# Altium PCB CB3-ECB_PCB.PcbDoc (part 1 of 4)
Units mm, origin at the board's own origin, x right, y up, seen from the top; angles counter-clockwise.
Board outline 195 x 139 mm, 4 copper layers (Top Layer, Layer 1, Layer 2, Bottom Layer), stack 1.56 mm thick; 363 components, 264 nets, 1430 pads, 630 vias.
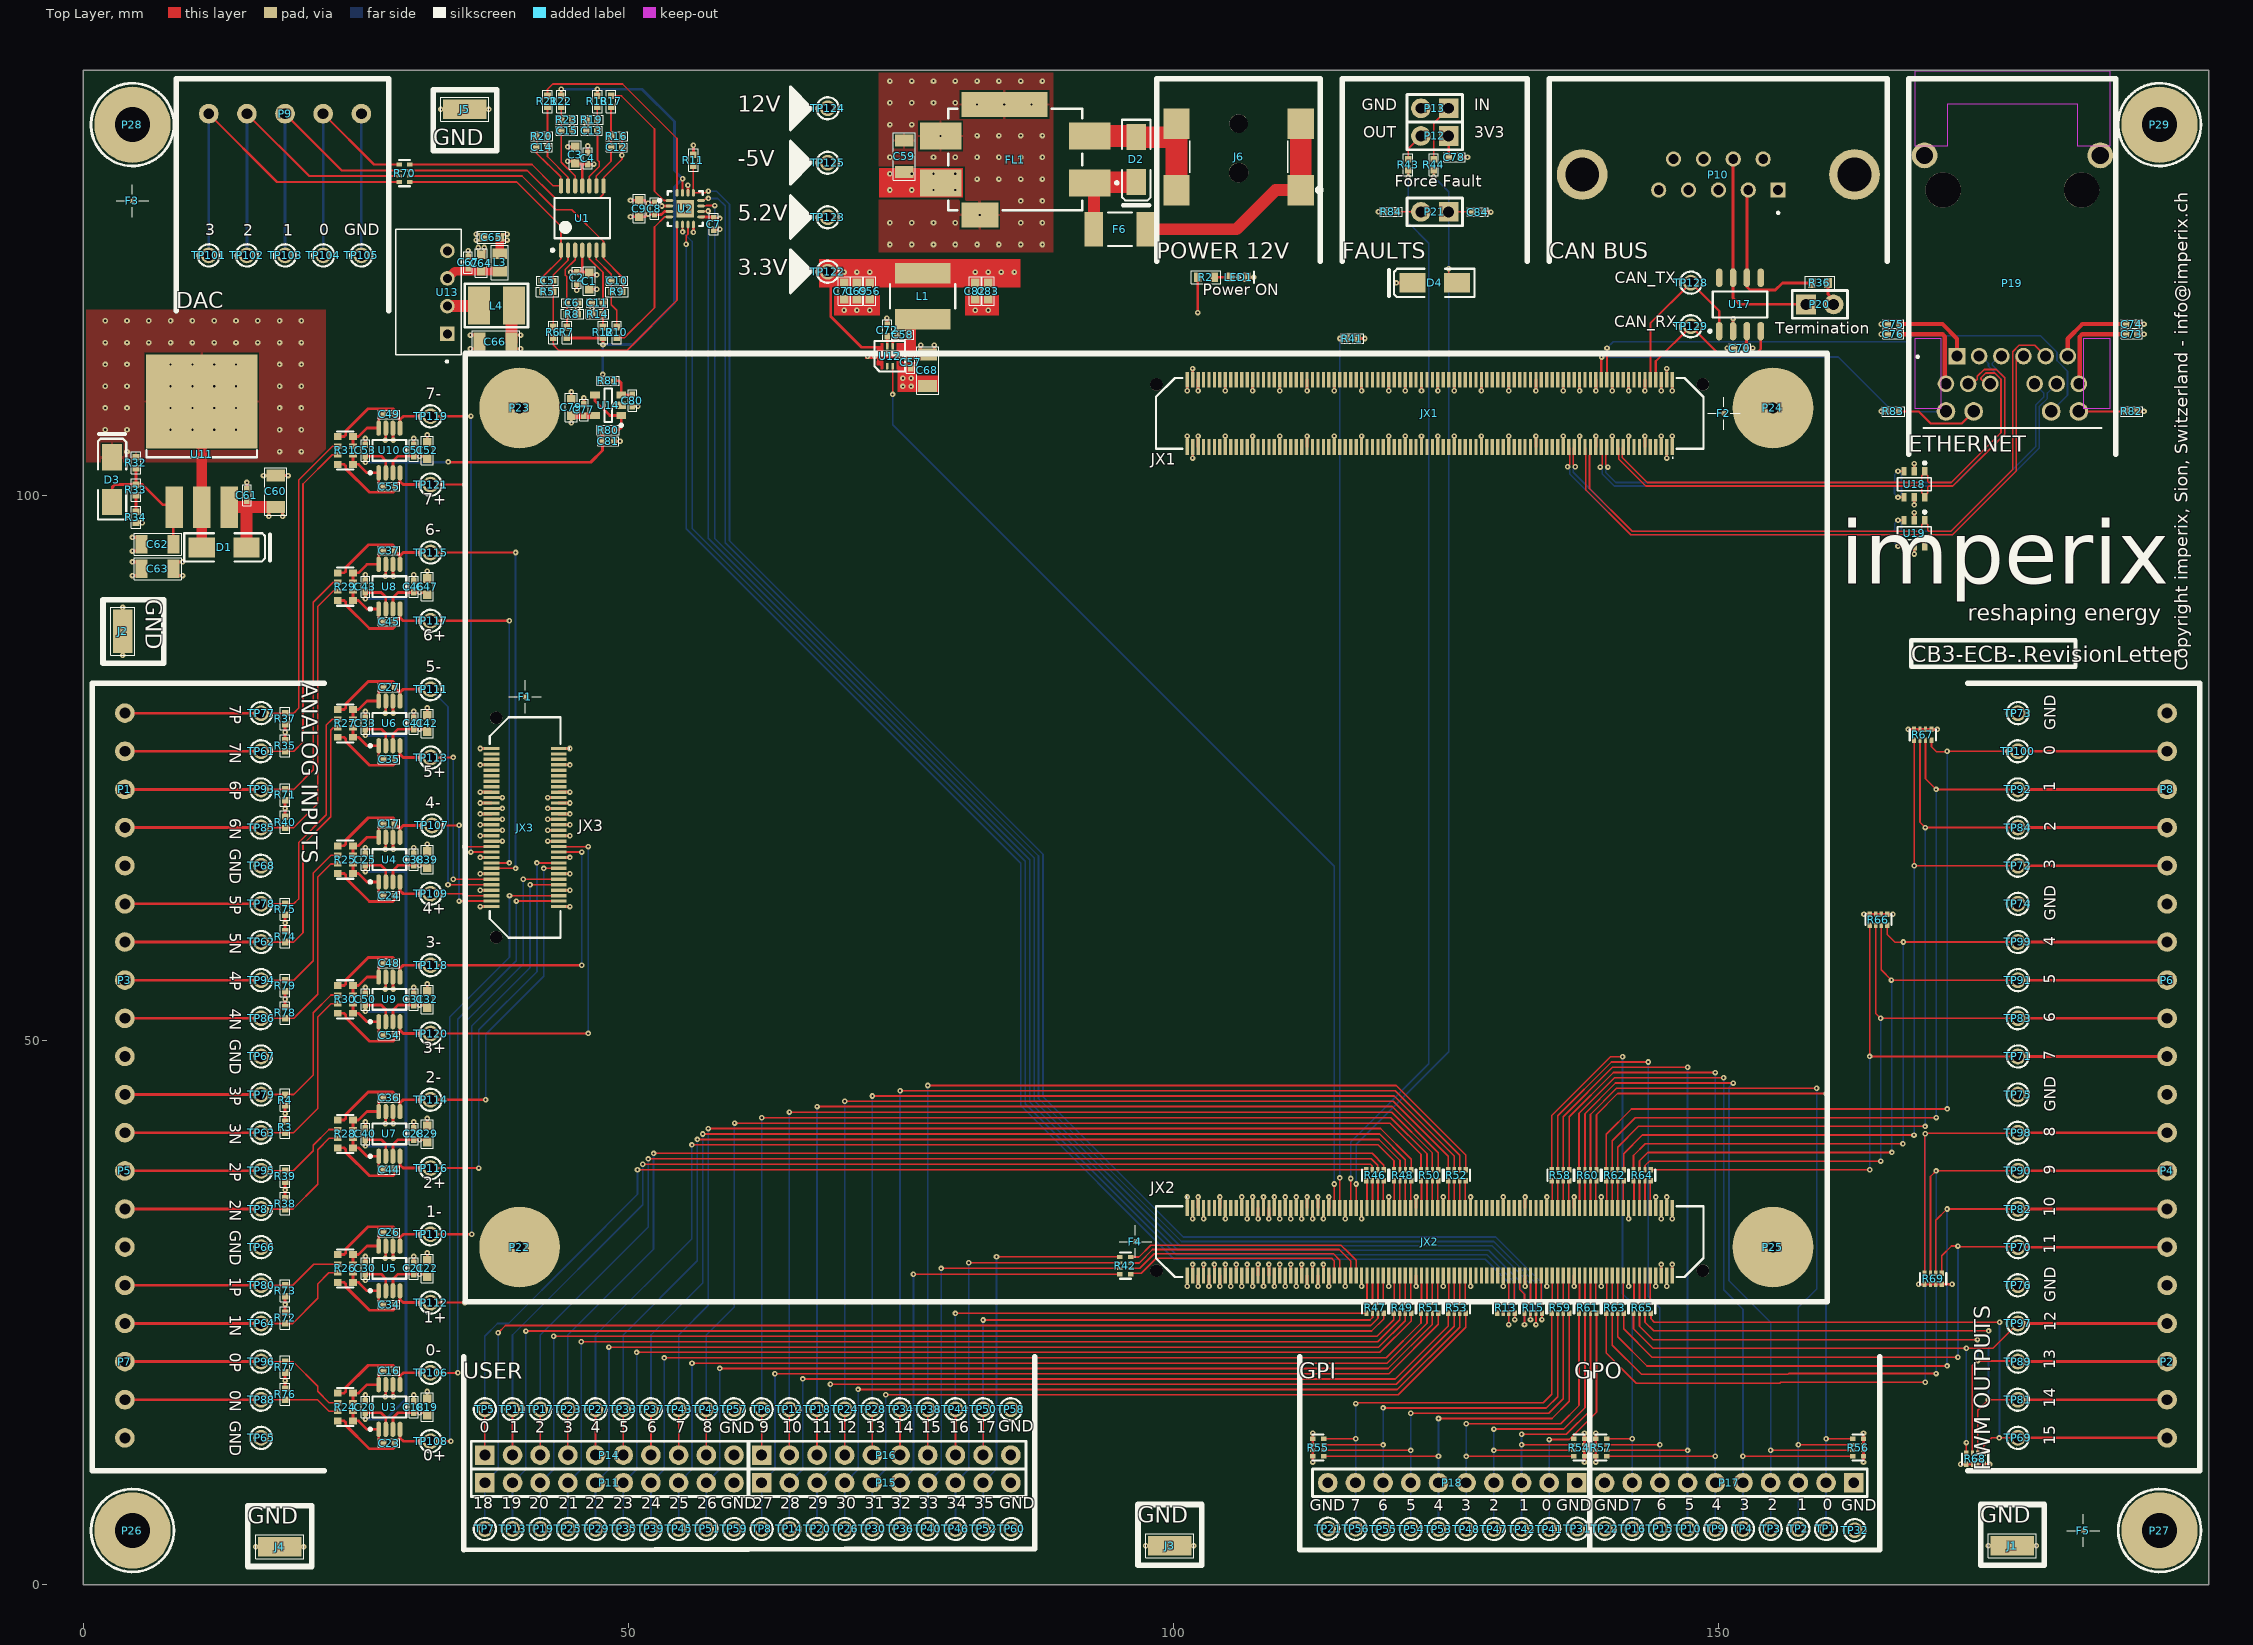
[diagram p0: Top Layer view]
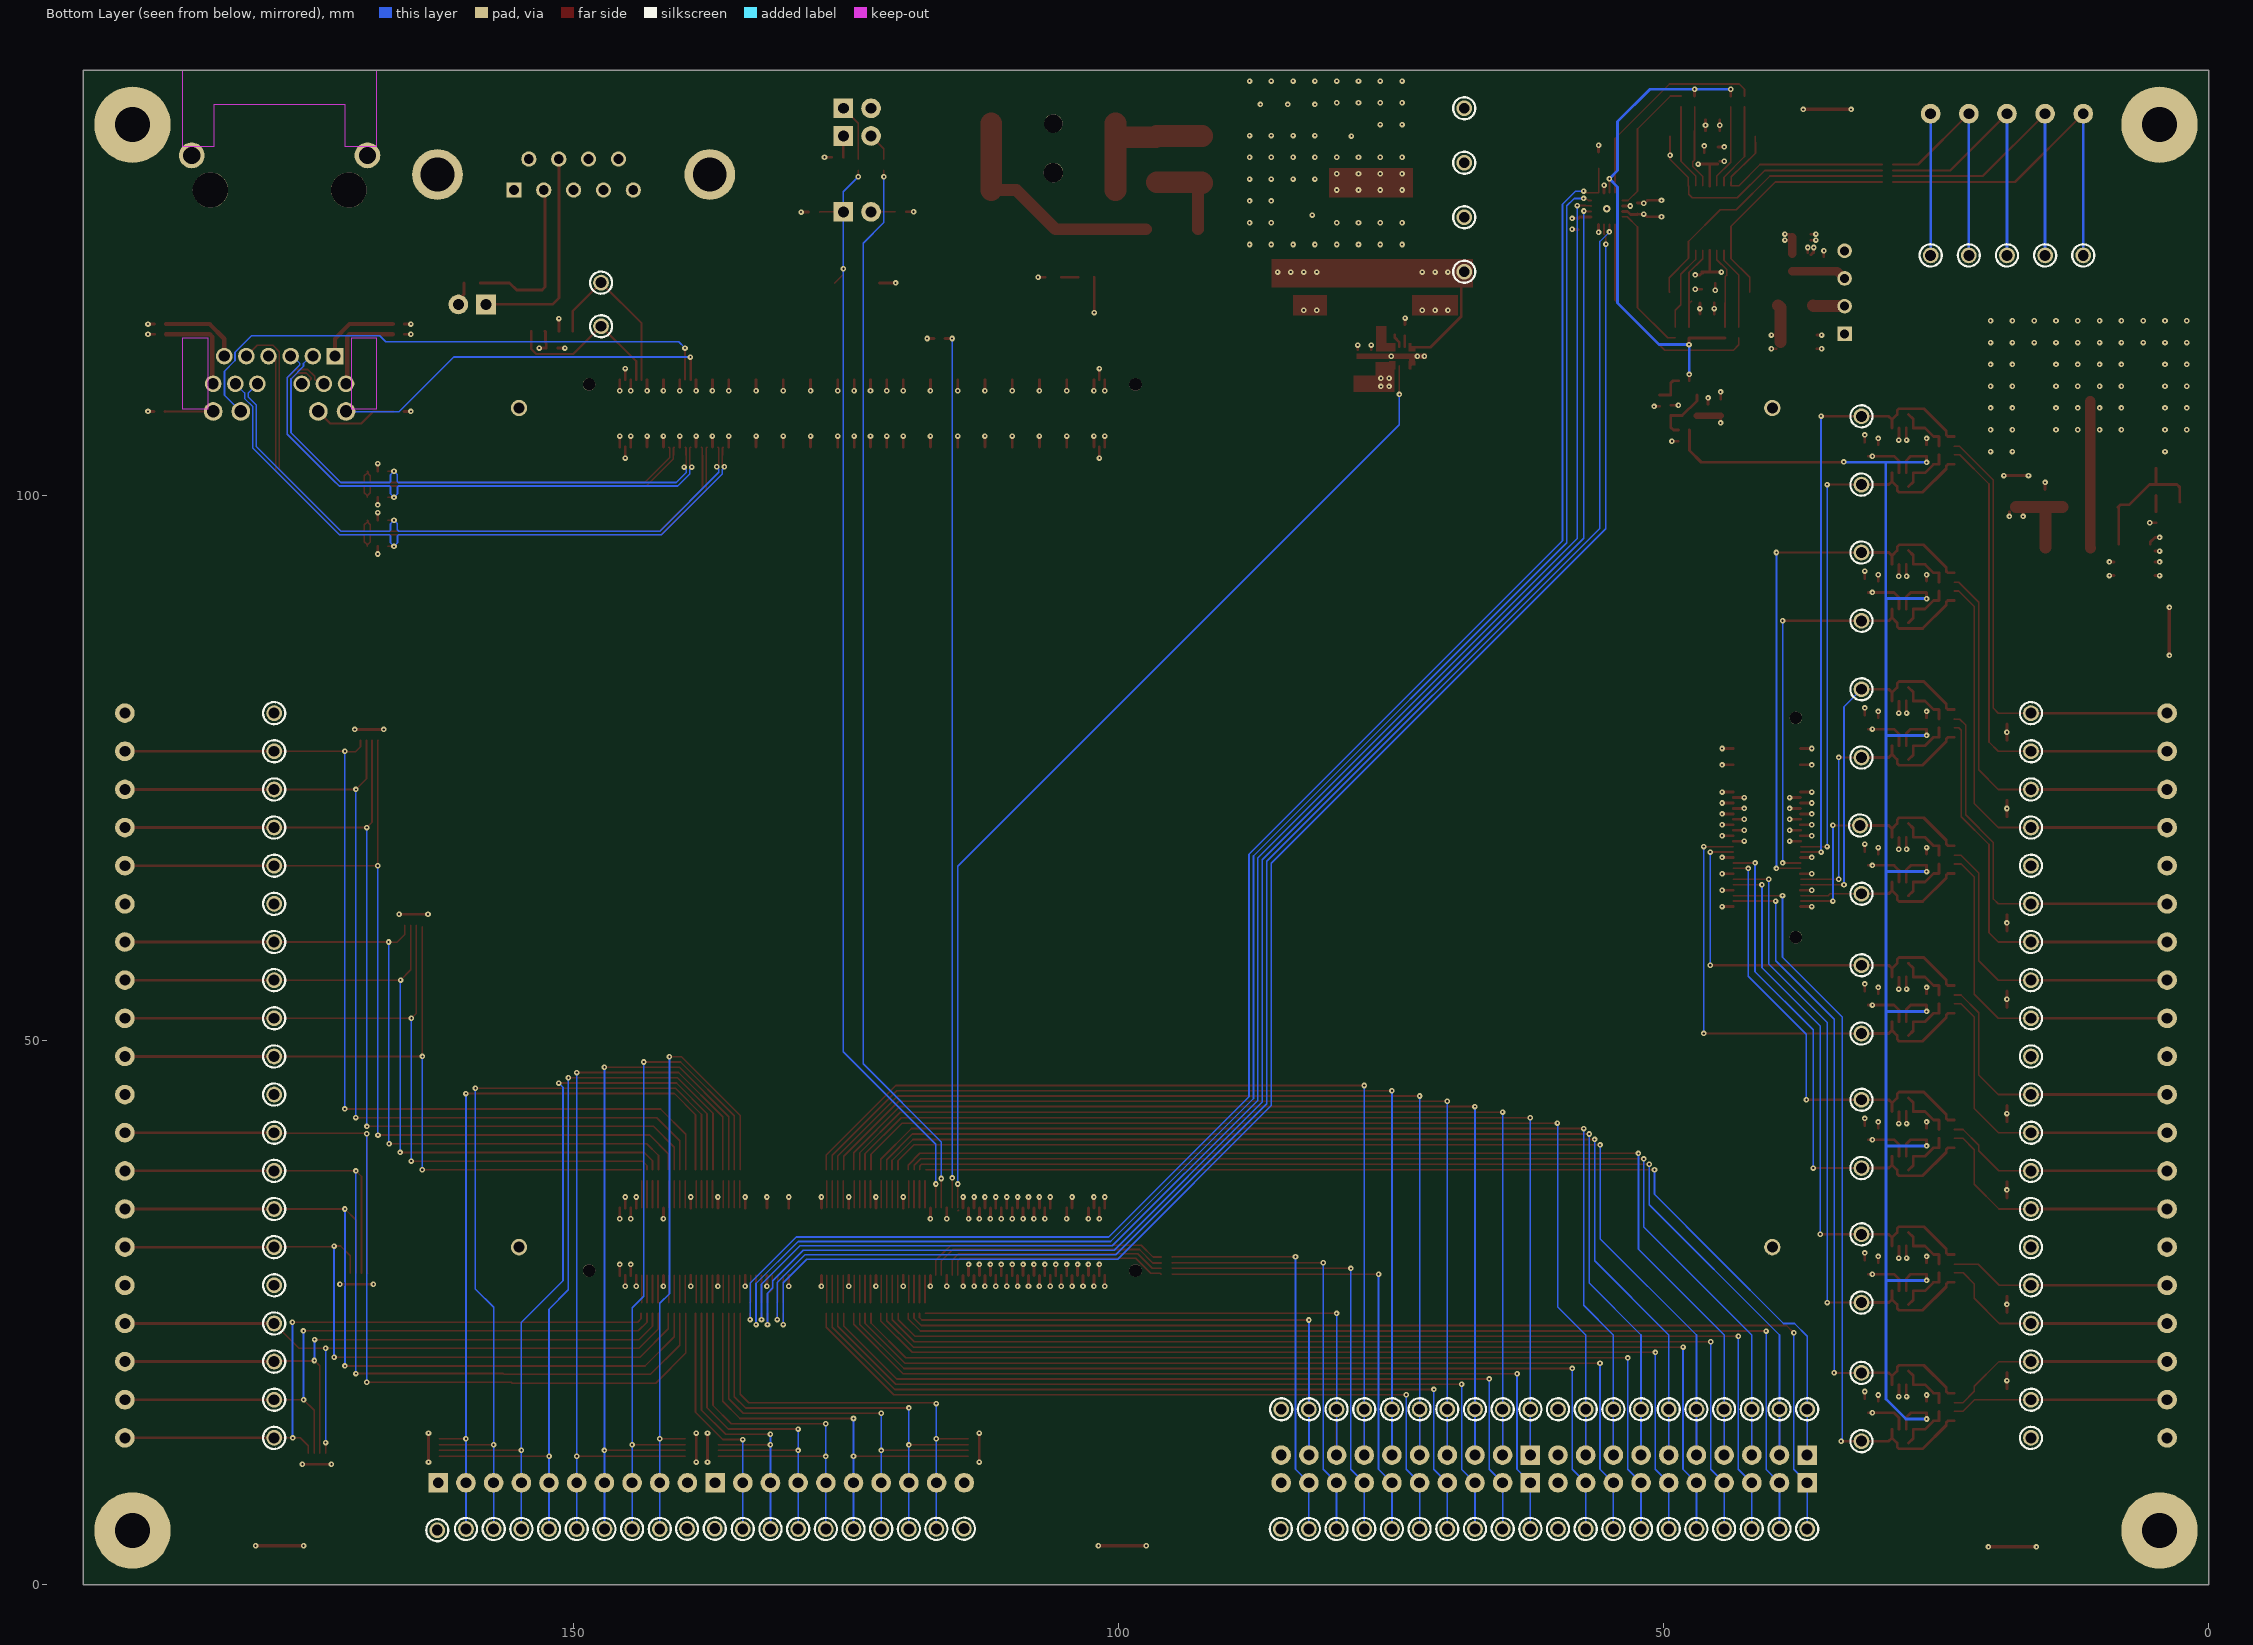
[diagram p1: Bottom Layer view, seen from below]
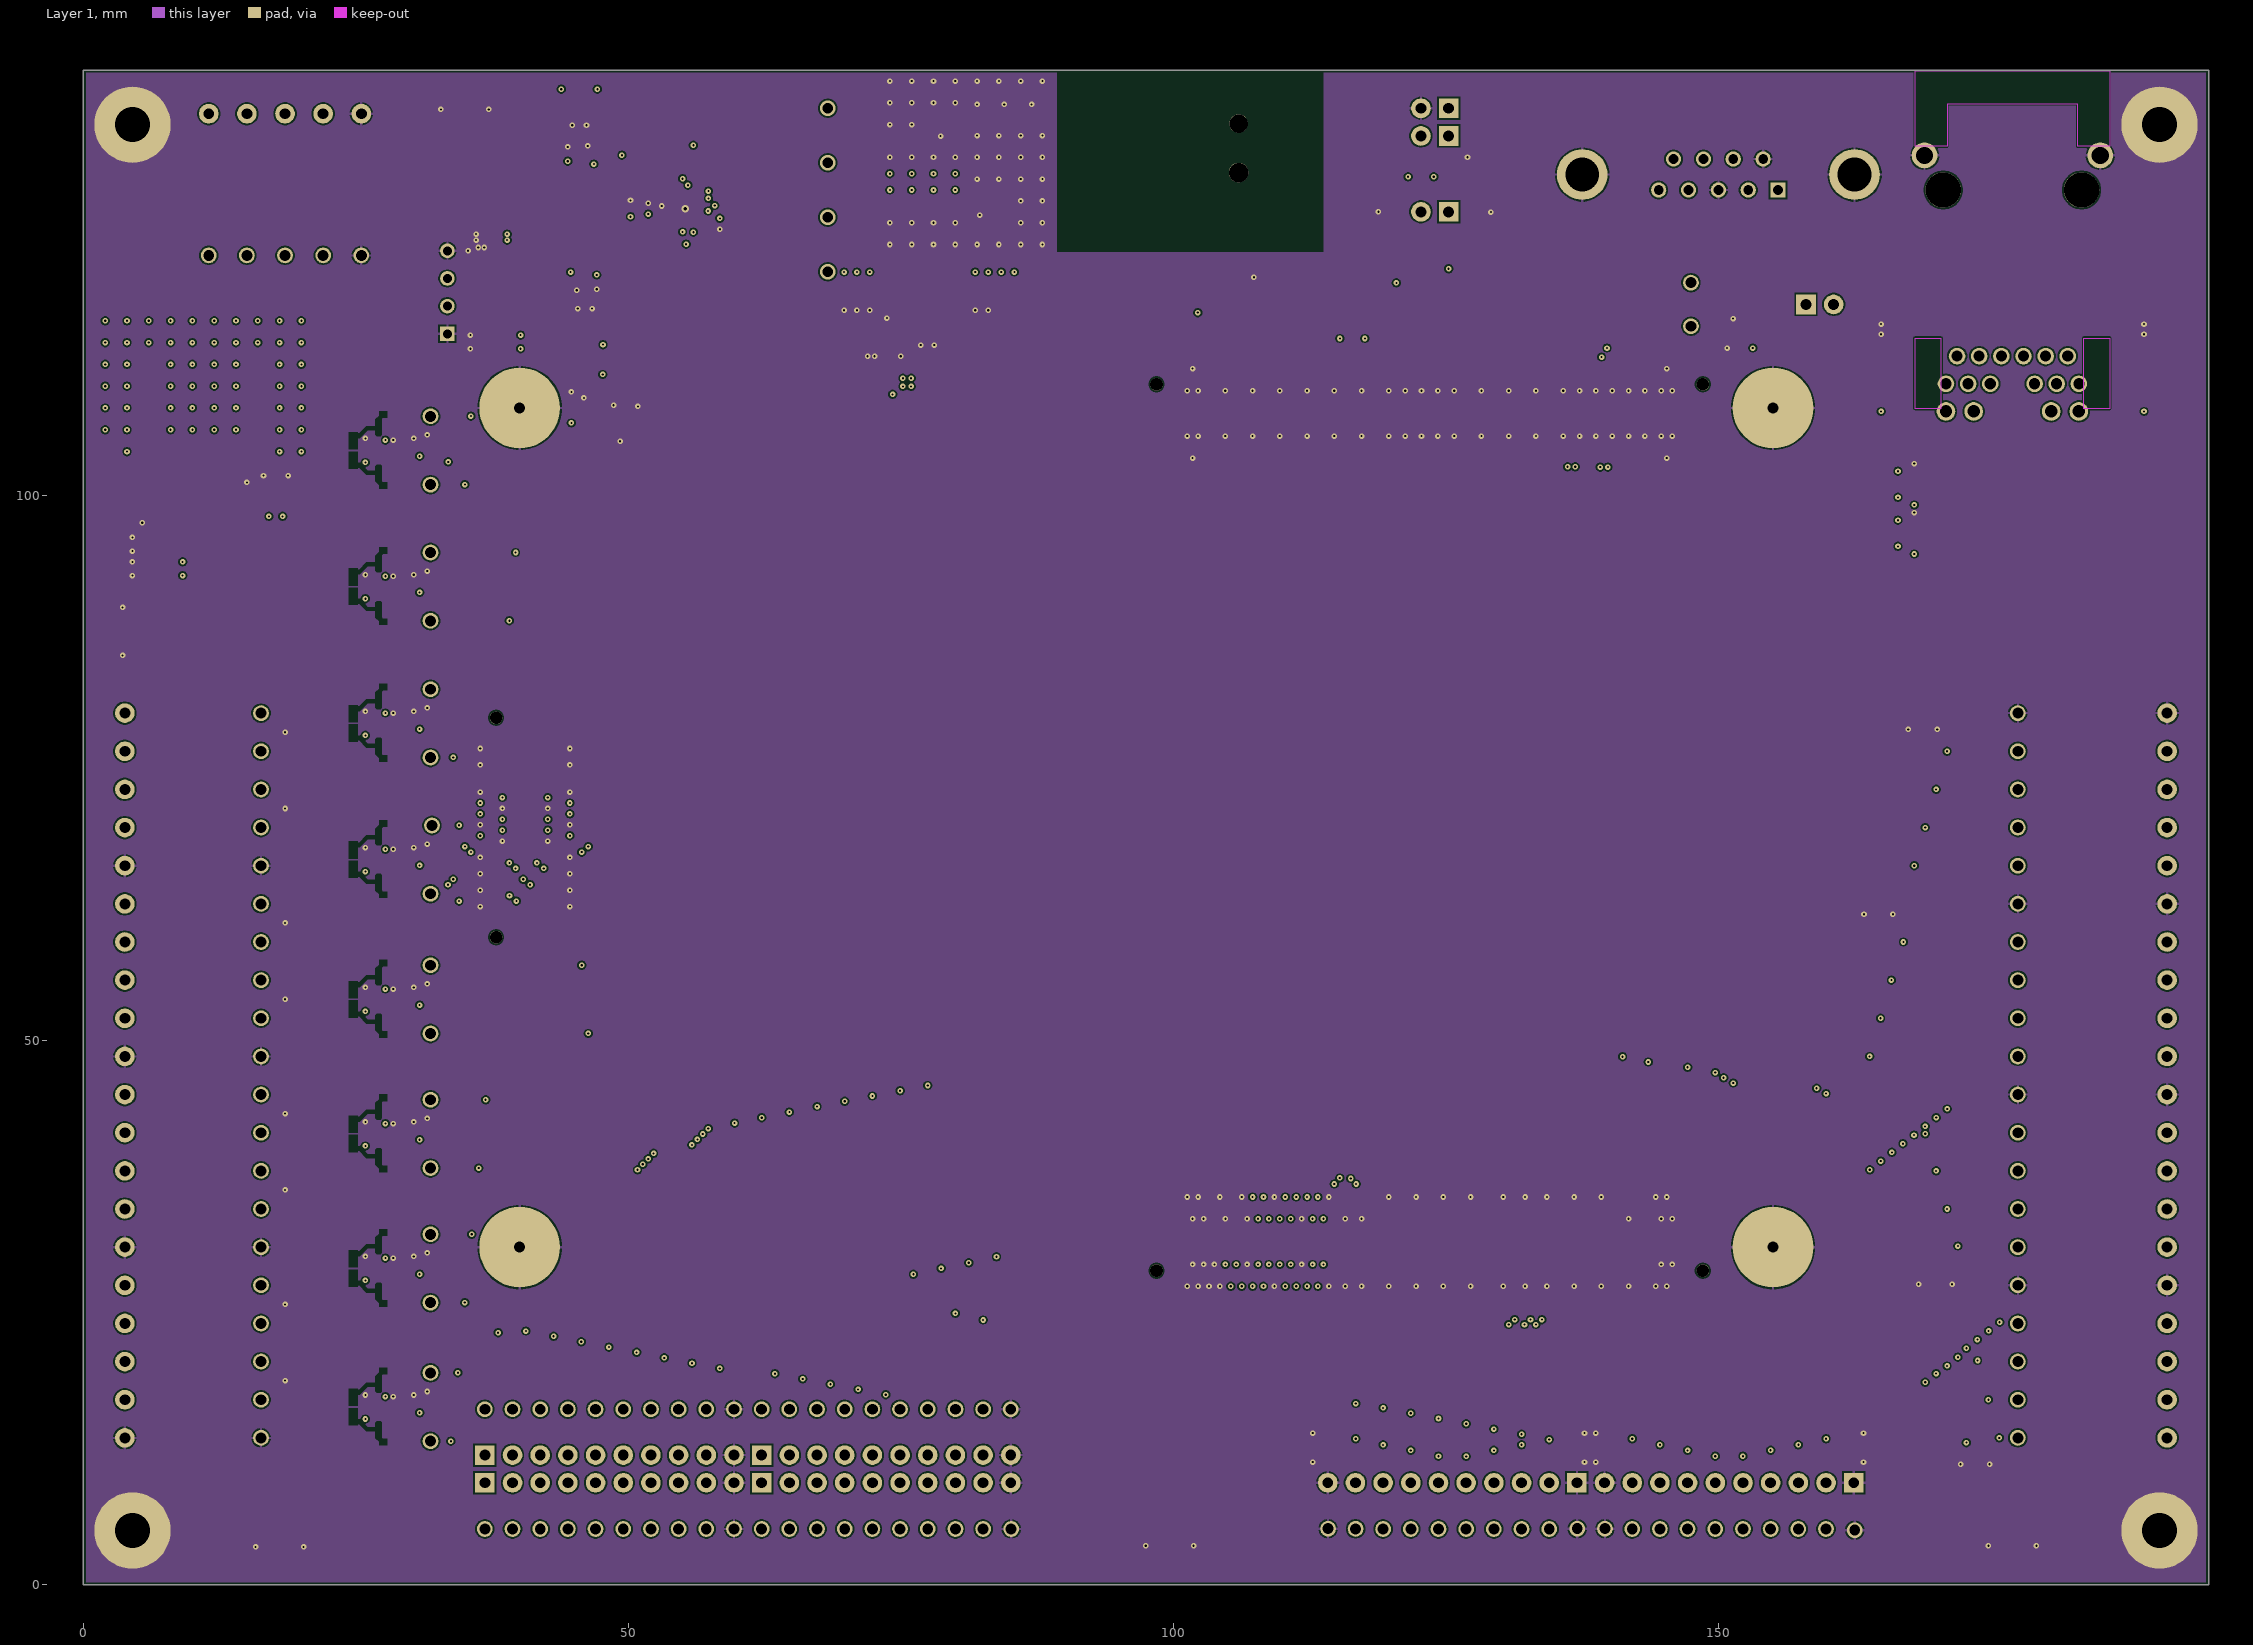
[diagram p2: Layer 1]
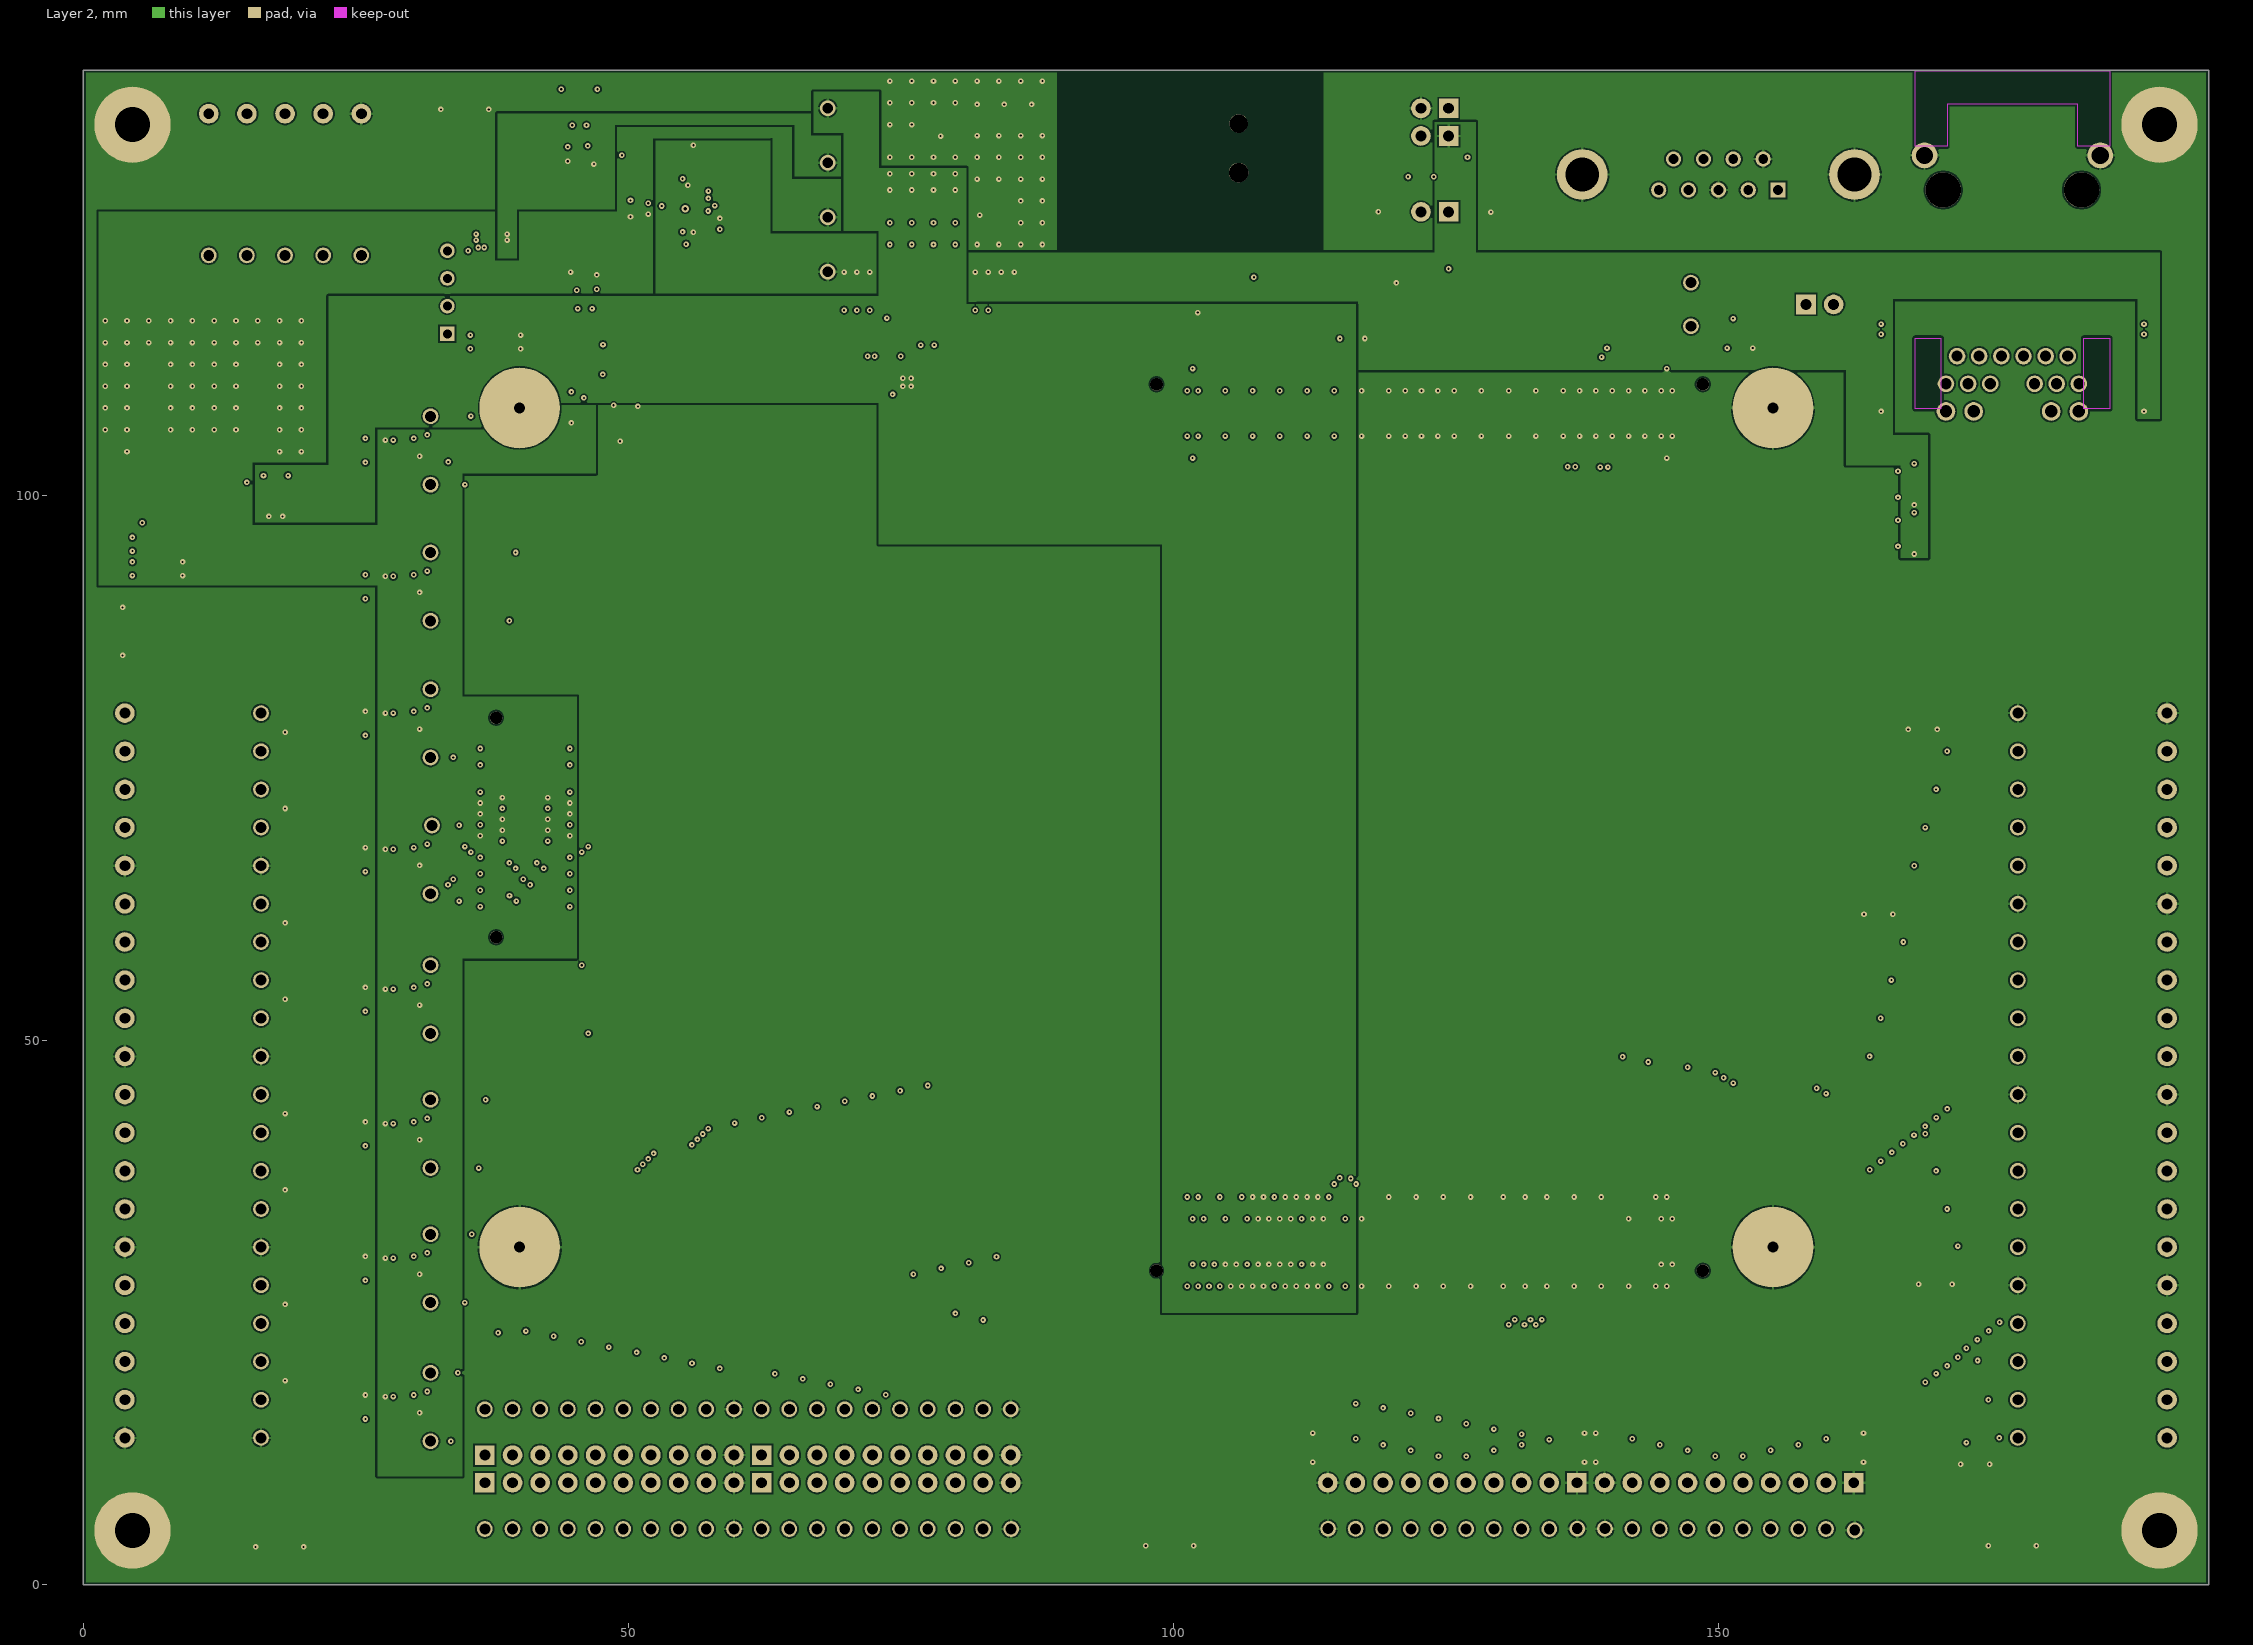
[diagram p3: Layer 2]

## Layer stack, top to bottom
Top Solder: solder mask 0.0102, Solder Resist, Dk 3.5
Top Layer: signal copper 0.035
Dielectric 1: prepreg 0.11, PP-006, Dk 4.29
Layer 1: signal copper 0.035
Dielectric4: dielectric 1.2, FR-4, Dk 4.8
Layer 2: signal copper 0.035
Dielectric 2: prepreg 0.11, PP-006, Dk 4.29
Bottom Layer: signal copper 0.035
Bottom Solder: solder mask 0.0102, Solder Resist, Dk 3.5

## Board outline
0,0 0,139 195,139 195,0

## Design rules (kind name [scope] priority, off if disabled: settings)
BoardOutlineClearance [All] p1: gap=0.25 ignorepadtopadclearanceinfootprint=FALSE
Clearance Clearance_Layer1 [OnLayer('Layer 2')] p1: gap=0.152 ignorepadtopadclearanceinfootprint=FALSE except(0.25: Fill-Fill Fill-Poly Fill-Region Poly-Poly Poly-Region Region-Region)
Clearance [All] p2: gap=0.152 ignorepadtopadclearanceinfootprint=FALSE
ComponentClearance [All] p1: gap=0 collisioncheckmode=3 verticalgap=2540 showdistances=FALSE
DiffPairsRouting [InDifferentialPairClass('All Differential Pairs')] p1: maxlimit=0.18 minlimit=0.114 mostfreqgap=0.18 toplayer_mingap=0.18 toplayer_minwidth=0.15 toplayer_maxwidth=0.15 toplayer_prefwidth=0.15 bottomlayer_mingap=0.18 bottomlayer_minwidth=0.15 bottomlayer_maxwidth=0.15 bottomlayer_prefwidth=0.15 impedanceprofiledriven=TRUE impedanceprofileid={5B398267-E329-4BF6-97D7-3C22107C88F5} impedanceprofilevalue=100.000000 maxuncoupledlength=12.7
HoleSize [All] p1: absolutevalues=TRUE maxlimit=5 minlimit=0.2 maxpercent=80.000 minpercent=20.000
HoleToHoleClearance [All] p1: gap=0.3 allowstackedmicrovias=TRUE
MinimumAnnularRing [All] p1: minimumring=0.152
MinimumSolderMaskSliver [All] p1 off: minsoldermaskwidth=0.254
PasteMaskExpansion PasteMaskExpansion_J5_nomask [InComponent('J5')] p1: expansion=-10
PasteMaskExpansion PasteMaskExpansion_BGA [HasFootprint('FGG484')] p2 off: expansion=-0.175
PasteMaskExpansion PasteMaskExpansion_5mm [((PadXSize_TopLayer > 4.99) and (PadYSize_TopLayer > 4.99)) or ((PadXSize_BottomLayer > 4.99) and (PadYSize_BottomLayer > 4.99))] p3 off: expansion=-1
PasteMaskExpansion PasteMaskExpansion_2mm5 [((PadXSize_TopLayer > 2.49) and (PadYSize_TopLayer > 2.49)) or ((PadXSize_BottomLayer > 2.49) and (PadYSize_BottomLayer > 2.49))] p4 off: expansion=-0.5
PasteMaskExpansion PasteMaskExpansion_1mm [((PadXSize_TopLayer > 0.99) and (PadYSize_TopLayer > 0.99)) or ((PadXSize_BottomLayer > 0.99) and (PadYSize_BottomLayer > 0.99))] p5 off: expansion=-0.2
PasteMaskExpansion PasteMaskExpansion_default [All] p6 off: expansion=-0.05
PermittedLayers [All] p1: toplayerpermitted=TRUE bottomlayerpermitted=TRUE
PlaneClearance [All] p1: clearance=0.152
PlaneConnect PlaneConnect_pad [InPadClass('All Pads')] p1: planeconnectstyle=Relief reliefexpansion=0.2 reliefentries=4 reliefconductorwidth=0.2 reliefairgap=0.2
PlaneConnect [All] p2: planeconnectstyle=Direct reliefexpansion=0.508 reliefentries=4 reliefconductorwidth=0.254 reliefairgap=0.254
PolygonConnect [All] p1: thpad.connectstyle=Relief thpad.reliefconductorwidth=0.25 thpad.reliefentries=4 thpad.polygonreliefangle="90 Angle" thpad.airgapwidth=0.15 smdpad.connectstyle=Relief smdpad.reliefconductorwidth=0.25 smdpad.reliefentries=4 smdpad.polygonreliefangle="90 Angle" smdpad.airgapwidth=0.15 via.connectstyle=Direct via.reliefconductorwidth=0.254 via.reliefentries=4 via.polygonreliefangle="90 Angle" via.airgapwidth=0.254
RoutingVias [All] p1: holewidth=0.2 width=0.45 viastyle="Through Hole" minholewidth=0.2 minwidth=0.4 maxholewidth=2 maxwidth=4
SMDNeckDown [All] p1 off: percent=95.000
SMDToCorner [All] p1: distance=0
SilkToSilkClearance [All] p1 off: silktosilkclearance=0.254
SilkToSolderMaskClearance [IsPad] p1 off: minsilkscreentomaskgap=0.254 clearancetoexposedcopper=TRUE
SolderMaskExpansion [All] p1: expansion=0.051 istentingtop=FALSE
Width Width_power [InNetClass('PWR')] p1: maxlimit=2 minlimit=0.25 preferedwidth=0.4
Width [All] p2: maxlimit=2 minlimit=0.152 preferedwidth=0.152
20 further rules are at their usual default settings.

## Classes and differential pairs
component class Power: C56 C57 C58 C59 C60 C61 C62 C63 C64 C65 C66 C67 C68 C69 C71 C72 C82 C83 D1 D2 D3 F1 F2 F3 F4 F5 F6 FL1 J6 L1 L3 L4 LED1 P22 P23 P24 P25 P26 P27 P28 P29 R2 R32 R33 R34 TP122 TP123 TP124 TP125 U11 U12 U13
component class BBoard-JX2: C78 C84 D4 JX2 P2 P4 P6 P8 P11 P12 P13 P14 P15 P16 P17 P18 P21 R41 R42 R43 R44 R46 R47 R48 R49 R50 R51 R52 R53 R54 R55 R56 R57 R58 R59 R60 R61 R62 R63 R64 R65 R66 R67 R68 R69 R84
component class BBoard-JX1: C70 C73 C74 C75 C76 JX1 P10 P19 P20 R36 R82 R83 TP128 TP129 U17 U18 U19
net class PWR: 3V3 5V2 +12V -5V GND NetC58_1 NetC64_1 NetD2_A NetD2_K NetF6_1 NetL4_2
component class ADC: C16 C17 C18 C19 C20 C21 C22 C23 C24 C25 C26 C27 C28 C29 C30 C31 C32 C33 C34 C35 C36 C37 C38 C39 C40 C41 C42 C43 C44 C45 C46 C47 C48 C49 C50 C51 C52 C53 C54 C55 C77 C79 C80 C81 JX3 P1 P3 P5 P7 R3 R4 R24 R25 R26 R27 R28 R29 R30 R31 R35 R37 R38 R39 R40 R71 R72 R73 R74 R75 R76 R77 R78 R79 R80 R81 TP106 TP107 TP108 TP109 TP110 TP111 TP112 TP113 TP114 TP115 TP116 TP117 TP118 TP119 TP120 TP121 U3 U4 U5 U6 U7 U8 U9 U10 U14
component class DAC: C1 C2 C3 C4 C5 C6 C7 C8 C9 C10 C11 C12 C13 C14 C15 P9 R5 R6 R7 R8 R9 R10 R11 R12 R13 R14 R15 R16 R17 R18 R19 R20 R21 R22 R23 R70 TP101 TP102 TP103 TP104 TP105 U1 U2
component class "Test points": J1 J2 J3 J4 J5 TP1 TP2 TP3 TP4 TP5 TP6 TP7 TP8 TP9 TP10 TP11 TP12 TP13 TP14 TP15 TP16 TP17 TP18 TP19 TP20 TP21 TP22 TP23 TP24 TP25 TP26 TP27 TP28 TP29 TP30 TP31 TP32 TP33 TP34 TP35 TP36 TP37 TP38 TP39 TP40 TP41 TP42 TP43 TP44 TP45 TP46 TP47 TP48 TP49 TP50 TP51 TP52 TP53 TP54 TP55 TP56 TP57 TP58 TP59 TP60 TP61 TP62 TP63 TP64 TP65 TP66 TP67 TP68 TP69 TP70 TP71 TP72 TP73 TP74 TP75 TP76 TP77 TP78 TP79 TP80 TP81 TP82 TP83 TP84 TP85 TP86 TP87 TP88 TP89 TP90 TP91 TP92 TP93 TP94 TP95 TP96 TP97 TP98 TP99 TP100
differential pair PHY_MDI3: +PHY_MDI3_P -PHY_MDI3_N
differential pair PHY_MDI2: +PHY_MDI2_P -PHY_MDI2_N
differential pair PHY_MDI1: +PHY_MDI1_P -PHY_MDI1_N
differential pair PHY_MDI0: +PHY_MDI0_P -PHY_MDI0_N

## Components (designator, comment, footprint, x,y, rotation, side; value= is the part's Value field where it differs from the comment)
C1 "CAP-10UF-10V-X5R-0603-10%" CAPC1608L(0603) 46.417,119.639 r90 top value=10uF
C2 "CAP-100NF-25V-X7R-0402-10%" CAPC1005L(0402) 45.272,119.942 r90 top value=100nF
C3 "CAP-10UF-10V-X5R-0603-10%" CAPC1608L(0603) 45.125,131.213 r90 top value=10uF
C4 "CAP-100NF-25V-X7R-0402-10%" CAPC1005L(0402) 46.27,130.91 r90 top value=100nF
C5 "CAP-56PF-50V-C0G-0402-1%" CAPC1005L(0402) 42.587,119.665 r180 top value=56pF
C6 "CAP-10NF-25V-X7R-0402-10%" CAPC1005L(0402) 44.865,117.633 r180 top value=10nF
C7 "CAP-100NF-25V-X7R-0402-10%" CAPC1005L(0402) 57.828,124.871 r90 top value=100nF
C8 "CAP-100NF-25V-X7R-0402-10%" CAPC1005L(0402) 52.4,126.3 r270 top value=100nF
C9 "CAP-10UF-10V-X5R-0603-10%" CAPC1608L(0603) 51,126.3 r270 top value=10uF
C10 "CAP-56PF-50V-C0G-0402-1%" CAPC1005L(0402) 48.963,119.665 r0 top value=56pF
C11 "CAP-10NF-25V-X7R-0402-10%" CAPC1005L(0402) 47.151,117.633 r0 top value=10nF
C12 "CAP-56PF-50V-C0G-0402-1%" CAPC1005L(0402) 48.941,131.908 r0 top value=56pF
C13 "CAP-10NF-25V-X7R-0402-10%" CAPC1005L(0402) 46.647,133.432 r0 top value=10nF
C14 "CAP-56PF-50V-C0G-0402-1%" CAPC1005L(0402) 42.057,131.908 r180 top value=56pF
C15 "CAP-10NF-25V-X7R-0402-10%" CAPC1005L(0402) 44.377,133.432 r180 top value=10nF
C16 "CAP-12PF-50V-C0G-0402-5%" CAPC1005L(0402) 28.049,19.638 r0 top value=12pF
C17 "CAP-12PF-50V-C0G-0402-5%" CAPC1005L(0402) 28.049,69.867 r0 top value=12pF
C18 "CAP-100NF-25V-X7R-0402-10%" CAPC1005L(0402) 30.305,16.331 r270 top value=100nF
C19 "CAP-10UF-10V-X5R-0603-10%" CAPC1608L(0603) 31.548,16.331 r270 top value=10uF
C20 "CAP-1UF-6.3V-X5R-0402-5%" CAPC1005L(0402) 25.875,16.331 r270 top value=1uF
C21 "CAP-100NF-25V-X7R-0402-10%" CAPC1005L(0402) 30.305,29.044 r270 top value=100nF
C22 "CAP-10UF-10V-X5R-0603-10%" CAPC1608L(0603) 31.548,29.044 r270 top value=10uF
C23 "CAP-12PF-50V-C0G-0402-5%" CAPC1005L(0402) 28.049,13.025 r0 top value=12pF
C24 "CAP-12PF-50V-C0G-0402-5%" CAPC1005L(0402) 28.049,63.253 r0 top value=12pF
C25 "CAP-1UF-6.3V-X5R-0402-5%" CAPC1005L(0402) 25.875,66.56 r270 top value=1uF
C26 "CAP-12PF-50V-C0G-0402-5%" CAPC1005L(0402) 28.049,32.351 r0 top value=12pF
C27 "CAP-12PF-50V-C0G-0402-5%" CAPC1005L(0402) 28.049,82.364 r0 top value=12pF
C28 "CAP-100NF-25V-X7R-0402-10%" CAPC1005L(0402) 30.305,41.389 r270 top value=100nF
C29 "CAP-10UF-10V-X5R-0603-10%" CAPC1608L(0603) 31.548,41.389 r270 top value=10uF
C30 "CAP-1UF-6.3V-X5R-0402-5%" CAPC1005L(0402) 25.875,29.044 r270 top value=1uF
C31 "CAP-100NF-25V-X7R-0402-10%" CAPC1005L(0402) 30.305,53.733 r270 top value=100nF
C32 "CAP-10UF-10V-X5R-0603-10%" CAPC1608L(0603) 31.548,53.733 r270 top value=10uF
C33 "CAP-1UF-6.3V-X5R-0402-5%" CAPC1005L(0402) 25.875,79.057 r270 top value=1uF
C34 "CAP-12PF-50V-C0G-0402-5%" CAPC1005L(0402) 28.049,25.737 r0 top value=12pF
C35 "CAP-12PF-50V-C0G-0402-5%" CAPC1005L(0402) 28.049,75.75 r0 top value=12pF
C36 "CAP-12PF-50V-C0G-0402-5%" CAPC1005L(0402) 28.049,44.695 r0 top value=12pF
C37 "CAP-12PF-50V-C0G-0402-5%" CAPC1005L(0402) 28.049,94.911 r0 top value=12pF
C38 "CAP-100NF-25V-X7R-0402-10%" CAPC1005L(0402) 30.305,66.56 r270 top value=100nF
C39 "CAP-10UF-10V-X5R-0603-10%" CAPC1608L(0603) 31.548,66.56 r270 top value=10uF
C40 "CAP-1UF-6.3V-X5R-0402-5%" CAPC1005L(0402) 25.875,41.389 r270 top value=1uF
C41 "CAP-100NF-25V-X7R-0402-10%" CAPC1005L(0402) 30.305,79.057 r270 top value=100nF
C42 "CAP-10UF-10V-X5R-0603-10%" CAPC1608L(0603) 31.548,79.057 r270 top value=10uF
C43 "CAP-1UF-6.3V-X5R-0402-5%" CAPC1005L(0402) 25.875,91.604 r270 top value=1uF
C44 "CAP-12PF-50V-C0G-0402-5%" CAPC1005L(0402) 28.049,38.082 r0 top value=12pF
C45 "CAP-12PF-50V-C0G-0402-5%" CAPC1005L(0402) 28.049,88.398 r0 top value=12pF
C46 "CAP-100NF-25V-X7R-0402-10%" CAPC1005L(0402) 30.305,91.604 r270 top value=100nF
C47 "CAP-10UF-10V-X5R-0603-10%" CAPC1608L(0603) 31.548,91.604 r270 top value=10uF
C48 "CAP-12PF-50V-C0G-0402-5%" CAPC1005L(0402) 28.049,57.04 r0 top value=12pF
C49 "CAP-12PF-50V-C0G-0402-5%" CAPC1005L(0402) 28.049,107.408 r0 top value=12pF
C50 "CAP-1UF-6.3V-X5R-0402-5%" CAPC1005L(0402) 25.875,53.733 r270 top value=1uF
C51 "CAP-100NF-25V-X7R-0402-10%" CAPC1005L(0402) 30.305,104.101 r270 top value=100nF
C52 "CAP-10UF-10V-X5R-0603-10%" CAPC1608L(0603) 31.548,104.101 r270 top value=10uF
C53 "CAP-1UF-6.3V-X5R-0402-5%" CAPC1005L(0402) 25.875,104.101 r270 top value=1uF
C54 "CAP-12PF-50V-C0G-0402-5%" CAPC1005L(0402) 28.049,50.426 r0 top value=12pF
C55 "CAP-12PF-50V-C0G-0402-5%" CAPC1005L(0402) 28.049,100.794 r0 top value=12pF
C56 "CAP-10UF-10V-X5R-0603-10%" CAPC1608L(0603) 72.15,118.725 r90 top value=10uF
C57 "CAP-100NF-25V-X7R-0402-10%" CAPC1005L(0402) 75.9,112.175 r270 top value=100nF
C58 "CAP-100NF-25V-X7R-0402-10%" CAPC1005L(0402) 75.2,114.725 r180 top value=100nF
C59 "CAP-10UF-25V-X5R-1206-10%" CAPC3216L(1206) 75.3,131.1 r270 top value=10uF
C60 "CAP-10UF-25V-X5R-1206-10%" CAPC3216L(1206) 17.65,100.35 r270 top value=10uF
C61 "CAP-100NF-25V-X7R-0402-10%" CAPC1005L(0402) 15,100 r270 top value=100nF
C62 "CAP-10UF-25V-X5R-1206-10%" CAPC3216L(1206) 6.8,95.5 r0 top value=10uF
C63 "CAP-10UF-25V-X5R-1206-10%" CAPC3216L(1206) 6.8,93.25 r0 top value=10uF
C64 "CAP-10UF-10V-X5R-0603-10%" CAPC1608L(0603) 36.5,121.3 r90 top value=10uF
C65 "CAP-10UF-10V-X5R-0603-10%" CAPC1608L(0603) 37.45,123.675 r180 top value=10uF
C66 "CAP-10UF-25V-X5R-1206-10%" CAPC3216L(1206) 37.808,114.062 r0 top value=10uF
C67 "CAP-100NF-25V-X7R-0402-10%" CAPC1005L(0402) 35.3,121.35 r90 top value=100nF
C68 "CAP-10UF-25V-X5R-1206-10%" CAPC3216L(1206) 77.45,111.475 r270 top value=10uF
C69 "CAP-10UF-10V-X5R-0603-10%" CAPC1608L(0603) 70.975,118.725 r90 top value=10uF
C70 "CAP-100NF-25V-X7R-0402-10%" CAPC1005L(0402) 152,113.5 r0 top value=100nF
C71 "CAP-10UF-10V-X5R-0603-10%" CAPC1608L(0603) 69.8,118.725 r90 top value=10uF
C72 "CAP-1UF-6.3V-X5R-0402-5%" CAPC1005L(0402) 73.75,115.125 r270 top value=1uF
C73 "CAP-100NF-25V-X7R-0402-10%" CAPC1005L(0402) 187.95,114.763 r180 top value=100nF
C74 "CAP-100NF-25V-X7R-0402-10%" CAPC1005L(0402) 187.95,115.7 r180 top value=100nF
C75 "CAP-100NF-25V-X7R-0402-10%" CAPC1005L(0402) 166.075,115.7 r0 top value=100nF
C76 "CAP-100NF-25V-X7R-0402-10%" CAPC1005L(0402) 166.075,114.763 r0 top value=100nF
C77 "CAP-100NF-25V-X7R-0402-10%" CAPC1005L(0402) 45.925,107.825 r270 top value=100nF
C78 "CAP-100NF-25V-X7R-0402-10%" CAPC1005L(0402) 125.8,131 r180 top value=100nF
C79 "CAP-10UF-10V-X5R-0603-10%" CAPC1608L(0603) 44.775,108.05 r270 top value=10uF
C80 "CAP-1UF-6.3V-X5R-0402-5%" CAPC1005L(0402) 50.375,108.675 r90 top value=1uF
C81 "CAP-1UF-6.3V-X5R-0402-5%" CAPC1005L(0402) 48.15,104.95 r180 top value=1uF
C82 "CAP-10UF-10V-X5R-0603-10%" CAPC1608L(0603) 81.825,118.725 r90 top value=10uF
C83 "CAP-10UF-10V-X5R-0603-10%" CAPC1608L(0603) 83.025,118.725 r90 top value=10uF
C84 "CAP-100NF-25V-X7R-0402-10%" CAPC1005L(0402) 127.95,125.975 r180 top value=100nF
D1 "MBRA340T3G" DO-214AC 12.91,95.2 r0 top
D2 "SMAJ15A-TR" DO-214AC 96.6,130.8 r270 top value=975pF
D3 "MBRA340T3G" DO-214AC 2.625,101.425 r90 top
D4 "MBRA340T3G" DO-214AC 124,119.475 r180 top
F1 "Fiducial" Fiducial050 40.53,81.505 r0 top
F2 "Fiducial" Fiducial050 150.53,107.505 r0 top
F3 "Fiducial" Fiducial050 4.5,127 r0 top
F4 "Fiducial" Fiducial050 96.53,31.505 r0 top
F5 "Fiducial" Fiducial050 183.5,5 r0 top
F6 "1812L110/16DR" "PTC Fuse(1812)" 95.1,124.4 r180 top value=180mR
FL1 "BNX024H01L" FP-BNX02-MFG 85.5,130.8 r180 top
J1 "1625854-1" TP-3216L(1206) 177,3.6 r0 top
J2 "1625854-1" TP-3216L(1206) 3.6,87.5 r270 top
J3 "1625854-1" TP-3216L(1206) 99.67,3.6 r0 top
J4 "1625854-1" TP-3216L(1206) 18,3.5 r180 top
J5 "1625854-1" TP-3216L(1206) 35,135.4 r0 top
J6 "PJ-002AH-SMT-TR" PJ-002AH-SMT-TR 111.7,128 r270 top locked
JX1 "BSH-090-01-F-D-A" BSH-090-01-F-D-A 123.53,107.505 r270 top locked
JX2 "BSH-090-01-F-D-A" BSH-090-01-F-D-A 123.53,31.505 r90 top locked
JX3 "BSH-030-01-L-D-A" BSH-030-01-L-D-A 40.53,69.505 r0 top locked
L1 "VLS6045EX-3R3N" VLS6045EX 77,118.25 r90 top value=3.3uH
L3 "ILHB0805ER601V" RESC2012L(0805) 38.2,121.35 r90 top value="600Ω 2A"
L4 "84223C" "Inductor 8400 Serie" 37.9,117.4 r180 top value=22uH
LED1 "LTST-C193KGKT-5A" LED0603_GREEN 106,120 r0 top
P1 "1988985" 1988985 3.8,73 r180 top locked
P2 "1988985" 1988985 191.2,20.5 r0 top locked
P3 "1988985" 1988985 3.8,55.5 r180 top locked
P4 "1988985" 1988985 191.2,38 r0 top locked
P5 "1988985" 1988985 3.8,38 r180 top locked
P6 "1988985" 1988985 191.2,55.5 r0 top locked
P7 "1988985" 1988985 3.8,20.5 r180 top locked
P8 "1988985" 1988985 191.2,73 r0 top locked
P9 "1988985" 1988985 18.5,135 r90 top locked
P10 "LD09P33E4GV00LF" LD09P33E4GV00LF 155.5,128 r180 top locked
P11 "M20-9731045" M20-9731045 36.834,9.381 r180 top
P12 "M20-9990245" M20-9990245 125.27,132.96 r0 top
P13 "M20-9990245" M20-9990245 125.27,135.5 r0 top
P14 "M20-9731045" M20-9731045 36.834,11.921 r180 top
P15 "M20-9731045" M20-9731045 62.234,9.381 r180 top
P16 "M20-9731045" M20-9731045 62.234,11.921 r180 top
P17 "M20-9731045" M20-9731045 162.437,9.381 r0 top
P18 "M20-9731045" M20-9731045 137.037,9.381 r0 top
P19 "0826-1X1T-43-F" BEL_0826-1X1T-43-F 177,128 r0 top locked
P20 "M20-9990245" M20-9990245 158.06,117.5 r180 top
P21 "M20-9990245" M20-9990245 125.27,126 r0 top
P22 "9771050360R" 9771050360R 40.03,31 r0 top locked
P23 "9771050360R" 9771050360R 40.03,108 r0 top locked
P24 "9771050360R" 9771050360R 155.03,108 r0 top locked
P25 "9771050360R" 9771050360R 155.03,31 r0 top locked
P26 "Spacer M3 connected" "Spacer M3 connected" 4.5,5 r0 top locked
P27 "Spacer M3 connected" "Spacer M3 connected" 190.5,5 r0 top locked
P28 "Spacer M3 connected" "Spacer M3 connected" 4.5,134 r0 top locked
P29 "Spacer M3 connected" "Spacer M3 connected" 190.5,134 r0 top locked
R2 "RES-1.8KΩ-1/8W-25PPM-0603-0.1%" RESC1608L(0603) 103,120 r180 top value=1.8kΩ
R3 "RES-1MΩ-1/16W-100PPM-0402-1%" RESC1005L(0402) 18.5,42 r270 top value=1MΩ
R4 "RES-1MΩ-1/16W-100PPM-0402-1%" RESC1005L(0402) 18.5,44.5 r90 top value=1MΩ
R5 "RES-6.19KΩ-1/16W-100PPM-0402-1%" RESC1005L(0402) 42.587,118.649 r180 top value=6.19kΩ
R6 "RES-3.09KΩ-1/16W-100PPM-0402-1%" RESC1005L(0402) 43.112,114.932 r270 top value=3.09kΩ
R7 "RES-3.09KΩ-1/16W-100PPM-0402-1%" RESC1005L(0402) 44.366,114.932 r270 top value=3.09kΩ
R8 "RES-6.19KΩ-1/16W-100PPM-0402-1%" RESC1005L(0402) 44.866,116.617 r180 top value=6.19kΩ
R9 "RES-6.19KΩ-1/16W-100PPM-0402-1%" RESC1005L(0402) 48.963,118.649 r0 top value=6.19kΩ
R10 "RES-3.09KΩ-1/16W-100PPM-0402-1%" RESC1005L(0402) 48.946,114.932 r270 top value=3.09kΩ
R11 "RES-6.19KΩ-1/16W-100PPM-0402-1%" RESC1005L(0402) 55.972,130.75 r90 top value=6.19kΩ
R12 "RES-3.09KΩ-1/16W-100PPM-0402-1%" RESC1005L(0402) 47.676,114.932 r270 top value=3.09kΩ
R13 "EXB-28V330JX" RESQUAD0804 130.53,25.42 r180 top value=33Ω
R14 "RES-6.19KΩ-1/16W-100PPM-0402-1%" RESC1005L(0402) 47.176,116.617 r0 top value=6.19kΩ
R15 "EXB-28V330JX" RESQUAD0804 133.03,25.42 r180 top value=33Ω
R16 "RES-6.19KΩ-1/16W-100PPM-0402-1%" RESC1005L(0402) 48.941,132.924 r0 top value=6.19kΩ
R17 "RES-3.09KΩ-1/16W-100PPM-0402-1%" RESC1005L(0402) 48.416,136.133 r90 top value=3.09kΩ
R18 "RES-3.09KΩ-1/16W-100PPM-0402-1%" RESC1005L(0402) 47.162,136.133 r90 top value=3.09kΩ
R19 "RES-6.19KΩ-1/16W-100PPM-0402-1%" RESC1005L(0402) 46.662,134.448 r0 top value=6.19kΩ
R20 "RES-6.19KΩ-1/16W-100PPM-0402-1%" RESC1005L(0402) 42.057,132.924 r180 top value=6.19kΩ
R21 "RES-3.09KΩ-1/16W-100PPM-0402-1%" RESC1005L(0402) 42.582,136.133 r90 top value=3.09kΩ
R22 "RES-3.09KΩ-1/16W-100PPM-0402-1%" RESC1005L(0402) 43.852,136.133 r90 top value=3.09kΩ
R23 "RES-6.19KΩ-1/16W-100PPM-0402-1%" RESC1005L(0402) 44.352,134.448 r180 top value=6.19kΩ
R24 "ACASA1002S1002P100" RESQUAD1206 24.041,16.331 r270 top value=10kΩ
R25 "ACASA1002S1002P100" RESQUAD1206 24.041,66.56 r270 top value=10kΩ
R26 "ACASA1002S1002P100" RESQUAD1206 24.041,29.044 r270 top value=10kΩ
R27 "ACASA1002S1002P100" RESQUAD1206 24.041,79.057 r270 top value=10kΩ
R28 "ACASA1002S1002P100" RESQUAD1206 24.041,41.389 r270 top value=10kΩ
R29 "ACASA1002S1002P100" RESQUAD1206 24.041,91.604 r270 top value=10kΩ
R30 "ACASA1002S1002P100" RESQUAD1206 24.041,53.733 r270 top value=10kΩ
R31 "ACASA1002S1002P100" RESQUAD1206 24.041,104.101 r270 top value=10kΩ
R32 "RES-249Ω-1/16W-100PPM-0402-1%" RESC1005L(0402) 4.825,102.975 r90 top value=249Ω
R33 "RES-777Ω-1/16W-25PPM-0402-0.1%" RESC1005L(0402) 4.825,100.475 r90 top value=777Ω
R34 "RES-1.6Ω-1/16WW-200PPM-0402-5%" RESC1005L(0402) 4.825,97.975 r90 top value=1.6Ω
R35 "RES-1MΩ-1/16W-100PPM-0402-1%" RESC1005L(0402) 18.5,77 r270 top value=1MΩ
R36 "RES-120Ω-1/8W-50PPM-0603-1%" RESC1608L(0603) 159.33,119.475 r0 top value=120Ω
R37 "RES-1MΩ-1/16W-100PPM-0402-1%" RESC1005L(0402) 18.5,79.5 r90 top value=1MΩ
R38 "RES-1MΩ-1/16W-100PPM-0402-1%" RESC1005L(0402) 18.5,35 r270 top value=1MΩ
R39 "RES-1MΩ-1/16W-100PPM-0402-1%" RESC1005L(0402) 18.5,37.5 r90 top value=1MΩ
R40 "RES-1MΩ-1/16W-100PPM-0402-1%" RESC1005L(0402) 18.5,70 r270 top value=1MΩ
R41 "RES-6.19KΩ-1/16W-100PPM-0402-1%" RESC1005L(0402) 116.44,114.375 r180 top value=6.19kΩ
R42 "EXB-28V330JX" RESQUAD0804 95.6,29.3 r270 top value=33Ω
R43 "RES-120Ω-1/16W-25PPM-0402-0.1%" RESC1005L(0402) 121.551,130.321 r90 top value=120Ω
R44 "RES-120Ω-1/16W-25PPM-0402-0.1%" RESC1005L(0402) 123.909,130.321 r90 top value=120Ω
R46 "EXB-28V330JX" RESQUAD0804 118.52,37.596 r180 top value=33Ω
R47 "EXB-28V330JX" RESQUAD0804 118.53,25.42 r0 top value=33Ω
R48 "EXB-28V330JX" RESQUAD0804 121.052,37.596 r180 top value=33Ω
R49 "EXB-28V330JX" RESQUAD0804 121.03,25.42 r0 top value=33Ω
R50 "EXB-28V330JX" RESQUAD0804 123.53,37.596 r180 top value=33Ω
R51 "EXB-28V330JX" RESQUAD0804 123.53,25.42 r0 top value=33Ω
R52 "EXB-28V330JX" RESQUAD0804 126.03,37.596 r180 top value=33Ω
R53 "EXB-28V330JX" RESQUAD0804 126.03,25.42 r0 top value=33Ω
R54 "EXB-28V103JX" RESQUAD0804 137.236,12.61 r270 top value=10kΩ
R55 "EXB-28V103JX" RESQUAD0804 113.296,12.61 r90 top value=10kΩ
R56 "EXB-28V103JX" RESQUAD0804 162.836,12.61 r270 top value=10kΩ
R57 "EXB-28V103JX" RESQUAD0804 139.268,12.61 r90 top value=10kΩ
R58 "EXB-28V330JX" RESQUAD0804 135.53,37.596 r0 top value=33Ω
R59 "EXB-28V330JX" RESQUAD0804 135.53,25.42 r0 top value=33Ω
R60 "EXB-28V330JX" RESQUAD0804 138.03,37.596 r0 top value=33Ω
R61 "EXB-28V330JX" RESQUAD0804 138.03,25.42 r0 top value=33Ω
R62 "EXB-28V330JX" RESQUAD0804 140.53,37.596 r180 top value=33Ω
R63 "EXB-28V330JX" RESQUAD0804 140.53,25.42 r0 top value=33Ω
R64 "EXB-28V330JX" RESQUAD0804 143.03,37.596 r180 top value=33Ω
R65 "EXB-28V330JX" RESQUAD0804 143.03,25.42 r0 top value=33Ω
R66 "EXB-28V103JX" RESQUAD0804 164.711,61.049 r0 top value=10kΩ
R67 "EXB-28V103JX" RESQUAD0804 168.775,78.004 r0 top value=10kΩ
R68 "EXB-28V103JX" RESQUAD0804 173.578,11.573 r180 top value=10kΩ
R69 "EXB-28V103JX" RESQUAD0804 169.727,28.101 r180 top value=10kΩ
R70 "EXB-28V330JX" RESQUAD0804 29.464,129.54 r90 top value=33Ω
R71 "RES-1MΩ-1/16W-100PPM-0402-1%" RESC1005L(0402) 18.5,72.5 r90 top value=1MΩ
R72 "RES-1MΩ-1/16W-100PPM-0402-1%" RESC1005L(0402) 18.5,24.5 r270 top value=1MΩ
R73 "RES-1MΩ-1/16W-100PPM-0402-1%" RESC1005L(0402) 18.5,27 r90 top value=1MΩ
R74 "RES-1MΩ-1/16W-100PPM-0402-1%" RESC1005L(0402) 18.5,59.5 r270 top value=1MΩ
R75 "RES-1MΩ-1/16W-100PPM-0402-1%" RESC1005L(0402) 18.5,62 r90 top value=1MΩ
R76 "RES-1MΩ-1/16W-100PPM-0402-1%" RESC1005L(0402) 18.5,17.5 r270 top value=1MΩ
R77 "RES-1MΩ-1/16W-100PPM-0402-1%" RESC1005L(0402) 18.5,20 r90 top value=1MΩ
R78 "RES-1MΩ-1/16W-100PPM-0402-1%" RESC1005L(0402) 18.5,52.5 r270 top value=1MΩ
R79 "RES-1MΩ-1/16W-100PPM-0402-1%" RESC1005L(0402) 18.5,55 r90 top value=1MΩ
R80 "RES-1.6Ω-1/16WW-200PPM-0402-5%" RESC1005L(0402) 48.15,105.975 r180 top value=1.6Ω
R81 "RES-100KΩ-1/16W-100PPM-0402-1%" RESC1005L(0402) 48.15,110.5 r0 top value=100kΩ
R82 "RES-249Ω-1/16W-100PPM-0402-1%" RESC1005L(0402) 187.95,107.68 r0 top value=249Ω
R83 "RES-249Ω-1/16W-100PPM-0402-1%" RESC1005L(0402) 166.075,107.68 r180 top value=249Ω
R84 "RES-777Ω-1/16W-25PPM-0402-0.1%" RESC1005L(0402) 120,126 r0 top value=777Ω
TP1 "5001" 5001 159.893,5.139 r0 top
TP2 "5001" 5001 157.353,5.139 r0 top
TP3 "5001" 5001 154.813,5.139 r0 top
TP4 "5001" 5001 152.273,5.139 r0 top
TP5 "5001" 5001 36.834,16.125 r0 top
TP6 "5001" 5001 62.234,16.125 r0 top
TP7 "5001" 5001 36.834,5.143 r0 top
TP8 "5001" 5001 62.234,5.143 r0 top
TP9 "5001" 5001 149.733,5.139 r0 top
TP10 "5001" 5001 147.193,5.139 r0 top
TP11 "5001" 5001 39.374,16.125 r0 top
TP12 "5001" 5001 64.774,16.125 r0 top
TP13 "5001" 5001 39.374,5.143 r0 top
TP14 "5001" 5001 64.774,5.143 r0 top
TP15 "5001" 5001 144.653,5.139 r0 top
TP16 "5001" 5001 142.113,5.139 r0 top
TP17 "5001" 5001 41.914,16.125 r0 top
TP18 "5001" 5001 67.314,16.125 r0 top
TP19 "5001" 5001 41.914,5.143 r0 top
TP20 "5001" 5001 67.314,5.143 r0 top
TP21 "5001" 5001 114.209,5.167 r180 top
TP22 "5001" 5001 139.609,5.167 r180 top
TP23 "5001" 5001 44.454,16.125 r0 top
TP24 "5001" 5001 69.854,16.125 r0 top
TP25 "5001" 5001 44.454,5.143 r0 top
TP26 "5001" 5001 69.854,5.143 r0 top
TP27 "5001" 5001 46.994,16.125 r0 top
TP28 "5001" 5001 72.394,16.125 r0 top
TP29 "5001" 5001 46.994,5.143 r0 top
TP30 "5001" 5001 72.394,5.143 r0 top
TP31 "5001" 5001 137.069,5.167 r180 top
TP32 "5001" 5001 162.53,5.03 r180 top
TP33 "5001" 5001 49.534,16.125 r0 top
TP34 "5001" 5001 74.934,16.125 r0 top
TP35 "5001" 5001 49.534,5.143 r0 top
TP36 "5001" 5001 74.934,5.143 r0 top
TP37 "5001" 5001 52.074,16.125 r0 top
TP38 "5001" 5001 77.474,16.125 r0 top
TP39 "5001" 5001 52.074,5.143 r0 top
TP40 "5001" 5001 77.474,5.143 r0 top
TP41 "5001" 5001 134.497,5.136 r0 top
TP42 "5001" 5001 131.957,5.136 r180 top
TP43 "5001" 5001 54.614,16.125 r0 top
TP44 "5001" 5001 80.014,16.125 r0 top
TP45 "5001" 5001 54.614,5.143 r0 top
TP46 "5001" 5001 80.014,5.143 r0 top
TP47 "5001" 5001 129.417,5.136 r180 top
TP48 "5001" 5001 126.877,5.136 r180 top
TP49 "5001" 5001 57.154,16.125 r0 top
TP50 "5001" 5001 82.554,16.125 r0 top
TP51 "5001" 5001 57.154,5.143 r0 top
TP52 "5001" 5001 82.554,5.143 r0 top
TP53 "5001" 5001 124.337,5.136 r180 top
TP54 "5001" 5001 121.797,5.136 r180 top
TP55 "5001" 5001 119.257,5.136 r180 top
TP56 "5001" 5001 116.733,5.151 r180 top
TP57 "5001" 5001 59.694,16.125 r0 top
TP58 "5001" 5001 85.094,16.125 r0 top
TP59 "5001" 5001 59.694,5.143 r0 top
TP60 "5001" 5001 85.13,5.143 r0 top
TP61 "5001" 5001 16.3,76.5 r270 top
TP62 "5001" 5001 16.3,59 r90 top
TP63 "5001" 5001 16.3,41.5 r90 top
TP64 "5001" 5001 16.3,24 r90 top
TP65 "5001" 5001 16.3,13.5 r90 top
TP66 "5001" 5001 16.3,31 r90 top
TP67 "5001" 5001 16.3,48.5 r90 top
TP68 "5001" 5001 16.3,66 r90 top
TP69 "5001" 5001 177.5,13.5 r270 top
TP70 "5001" 5001 177.5,31 r90 top
TP71 "5001" 5001 177.5,48.5 r270 top
TP72 "5001" 5001 177.5,66 r90 top
TP73 "5001" 5001 177.5,80 r90 top
TP74 "5001" 5001 177.5,62.5 r90 top
TP75 "5001" 5001 177.5,45 r90 top
TP76 "5001" 5001 177.5,27.5 r90 top
TP77 "5001" 5001 16.3,80 r90 top
TP78 "5001" 5001 16.3,62.5 r90 top
TP79 "5001" 5001 16.3,45 r90 top
TP80 "5001" 5001 16.3,27.5 r90 top
TP81 "5001" 5001 177.5,17 r270 top
TP82 "5001" 5001 177.5,34.5 r270 top
TP83 "5001" 5001 177.5,52 r270 top
TP84 "5001" 5001 177.5,69.5 r90 top
TP85 "5001" 5001 16.3,69.5 r90 top
TP86 "5001" 5001 16.3,52 r90 top
TP87 "5001" 5001 16.3,34.5 r90 top
TP88 "5001" 5001 16.3,17 r90 top
TP89 "5001" 5001 177.5,20.5 r270 top
TP90 "5001" 5001 177.5,38 r270 top
TP91 "5001" 5001 177.5,55.5 r270 top
TP92 "5001" 5001 177.5,73 r90 top
TP93 "5001" 5001 16.3,73 r90 top
TP94 "5001" 5001 16.3,55.5 r90 top
TP95 "5001" 5001 16.3,38 r90 top
TP96 "5001" 5001 16.3,20.5 r90 top
TP97 "5001" 5001 177.5,24 r270 top
TP98 "5001" 5001 177.5,41.5 r270 top
TP99 "5001" 5001 177.5,59 r270 top
TP100 "5001" 5001 177.5,76.5 r90 top
TP101 "5001" 5001 11.5,122 r90 top
TP102 "5001" 5001 15,122 r90 top
TP103 "5001" 5001 18.5,122 r90 top
TP104 "5001" 5001 22,122 r90 top
TP105 "5001" 5001 25.5,122 r90 top
TP106 "5001" 5001 31.852,19.465 r90 top
TP107 "5001" 5001 31.979,69.694 r90 top
TP108 "5001" 5001 31.852,13.198 r90 top
TP109 "5001" 5001 31.852,63.426 r90 top
TP110 "5001" 5001 31.852,32.178 r90 top
TP111 "5001" 5001 31.852,82.191 r90 top
TP112 "5001" 5001 31.852,25.91 r90 top
TP113 "5001" 5001 31.852,75.923 r90 top
TP114 "5001" 5001 31.852,44.522 r90 top
TP115 "5001" 5001 31.852,94.738 r90 top
TP116 "5001" 5001 31.852,38.255 r90 top
TP117 "5001" 5001 31.852,88.471 r90 top
TP118 "5001" 5001 31.852,56.867 r90 top
TP119 "5001" 5001 31.852,107.235 r90 top
TP120 "5001" 5001 31.852,50.599 r90 top
TP121 "5001" 5001 31.852,100.967 r90 top
TP122 "5001" 5001 68.3,120.5 r180 top
TP123 "5001" 5001 68.3,125.5 r90 top
TP124 "5001" 5001 68.3,135.5 r90 top
TP125 "5001" 5001 68.3,130.5 r0 top
TP128 "5001" 5001 147.5,119.5 r90 top
TP129 "5001" 5001 147.5,115.5 r90 top
U1 "OPA4205APWT" TSSOP65P640-14N 45.771,125.426 r90 top
U2 "AD5685RBCPZ-RL7" QFN50P300X300-16WAL 55.222,126.284 r0 top
U3 "THS4551IDGKT" TSOP65P490-8AL 28.072,16.331 r90 top
U4 "THS4551IDGKT" TSOP65P490-8AL 28.072,66.56 r90 top
U5 "THS4551IDGKT" TSOP65P490-8AL 28.072,29.044 r90 top
U6 "THS4551IDGKT" TSOP65P490-8AL 28.072,79.057 r90 top
U7 "THS4551IDGKT" TSOP65P490-8AL 28.072,41.389 r90 top
U8 "THS4551IDGKT" TSOP65P490-8AL 28.072,91.604 r90 top
U9 "THS4551IDGKT" TSOP65P490-8AL 28.072,53.733 r90 top
U10 "THS4551IDGKT" TSOP65P490-8AL 28.072,104.101 r90 top
U11 "LM317KTTR" TO263-3 10.86,98.9 r0 top
U12 "LMR43610MSC3RPERQ1" LMR43610MSC3RPERQ1 74,112.75 r90 top
U13 "ROE-1205S" ROE 31.649,118.679 r90 top
U14 "NCS325SN2T1G" SOT23-5AL 48.15,108.25 r180 top
U17 "SN65HVD232DR" SOIC127P600-8AL 152,117.5 r90 top
U18 "HDMIULC6-4SC6" SOT23-6N 168,101 r270 top value=1pF
U19 "HDMIULC6-4SC6" SOT23-6N 168,96.5 r270 top value=1pF

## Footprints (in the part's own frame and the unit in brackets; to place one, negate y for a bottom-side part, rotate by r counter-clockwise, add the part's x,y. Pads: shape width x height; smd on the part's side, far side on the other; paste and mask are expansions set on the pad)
5001 [mm] "Black PC Test Point, Miniature Phosphor Bronze Silver Plating Through Hole Mounting Type"
  round 1.45 hole 1: 1(0,0)
  silkscreen extent -1.01,-1.02 1.02,1.02, body extent -1.27,-1.26 1.27,1.26, height 4.59
1988985 [mm] "Conn PC Terminal Block 5 POS 3.5mm Solder Thru-Hole 17.5A"
  round 1.8 hole 1: 1(0,7) 2(0,3.5) 3(0,0) 4(0,-3.5) 5(0,-7)
  body extent -8.83,-8.81 2.37,9.26, height 10.34
9771050360R [mm] "WA-SMSE SMT Steel Spacer, M3 Thread External"
  round 7.4 / inner round 7.4 / far side round 1.5 hole 1: 0(0,0)
  body extent -3,-3 3,3, height 11
BEL_0826-1X1T-43-F [mil] "Conn Modular Jack RCP 12 POS 2.03mm Solder RA Thru-Hole 16 Terminal 1 Port Tray"
  rect 60x60 / inner round 60 / far side rect 60x60 hole 40: 1(-200,-600)
  round 60 hole 40: 2(-120,-600) 3(-40,-600) 4(40,-600) 5(120,-600) 6(200,-600) 7(-240,-700) 8(-160,-700) 9(-80,-700) 10(80,-700) 11(160,-700) 12(240,-700)
  round 67.5 hole 45: 13(-240,-800) 14(-140,-800) 15(140,-800) 16(240,-800)
  round 128 hole 128 unplated: H1(-250,0) H2(250,0)
  round 93 hole 62: S1(-317.5,125) S2(317.5,125)
  Keep-Out Layer region: 351,158 236,158 236,310 -236,310 -236,158 -351,158 -351,430 351,430
  Keep-Out Layer region: -258,-790 -351,-790 -351,-535 -258,-535
  Keep-Out Layer region: 351,-790 258,-790 258,-535 351,-535
  silkscreen extent -346,-860 321,-598, body extent -374,-859 374,456, height 590
BSH-030-01-L-D-A [mm] "Conn Micro Socket SKT 60 POS 0.5mm Solder ST SMD Automotive Tray"
  rect 1.448x0.305 smd: 1(3.095,7.25) 2(3.095,6.75) 3(3.095,6.25) 4(3.095,5.75) 5(3.095,5.25) 6(3.095,4.75) 7(3.095,4.25) 8(3.095,3.75) 9(3.095,3.25) 10(3.095,2.75) 11(3.095,2.25) 12(3.095,1.75) 13(3.095,1.25) 14(3.095,0.75) 15(3.095,0.25) 16(3.095,-0.25) 17(3.095,-0.75) 18(3.095,-1.25) 19(3.095,-1.75) 20(3.095,-2.25) 21(3.095,-2.75) 22(3.095,-3.25) 23(3.095,-3.75) 24(3.095,-4.25) 25(3.095,-4.75) 26(3.095,-5.25) 27(3.095,-5.75) 28(3.095,-6.25) 29(3.095,-6.75) 30(3.095,-7.25) 31(-3.095,-7.25) 32(-3.095,-6.75) 33(-3.095,-6.25) 34(-3.095,-5.75) 35(-3.095,-5.25) 36(-3.095,-4.75) 37(-3.095,-4.25) 38(-3.095,-3.75) 39(-3.095,-3.25) 40(-3.095,-2.75) 41(-3.095,-2.25) 42(-3.095,-1.75) 43(-3.095,-1.25) 44(-3.095,-0.75) 45(-3.095,-0.25) 46(-3.095,0.25) 47(-3.095,0.75) 48(-3.095,1.25) 49(-3.095,1.75) 50(-3.095,2.25) 51(-3.095,2.75) 52(-3.095,3.25) 53(-3.095,3.75) 54(-3.095,4.25) 55(-3.095,4.75) 56(-3.095,5.25) 57(-3.095,5.75) 58(-3.095,6.25) 59(-3.095,6.75) 60(-3.095,7.25)
  round 1.15 hole 1.15 unplated paste-2539.97 mask+0: NC(-2.666,-10.065) NC(-2.666,10.065)
  silkscreen extent -3.25,-10.12 4.12,10.12, body extent -3.75,-10.64 3.75,10.64, height 3.25
BSH-090-01-F-D-A [mm] "Conn Micro Socket SKT 180 POS 0.5mm Solder ST SMD Automotive Tray"
  rect 1.448x0.305 smd: 1(3.095,22.25) 2(3.095,21.75) 3(3.095,21.25) 4(3.095,20.75) 5(3.095,20.25) 6(3.095,19.75) 7(3.095,19.25) 8(3.095,18.75) 9(3.095,18.25) 10(3.095,17.75) 11(3.095,17.25) 12(3.095,16.75) 13(3.095,16.25) 14(3.095,15.75) 15(3.095,15.25) 16(3.095,14.75) 17(3.095,14.25) 18(3.095,13.75) 19(3.095,13.25) 20(3.095,12.75) 21(3.095,12.25) 22(3.095,11.75) 23(3.095,11.25) 24(3.095,10.75) 25(3.095,10.25) 26(3.095,9.75) 27(3.095,9.25) 28(3.095,8.75) 29(3.095,8.25) 30(3.095,7.75) 31(3.095,7.25) 32(3.095,6.75) 33(3.095,6.25) 34(3.095,5.75) 35(3.095,5.25) 36(3.095,4.75) 37(3.095,4.25) 38(3.095,3.75) 39(3.095,3.25) 40(3.095,2.75) 41(3.095,2.25) 42(3.095,1.75) 43(3.095,1.25) 44(3.095,0.75) 45(3.095,0.25) 46(3.095,-0.25) 47(3.095,-0.75) 48(3.095,-1.25) 49(3.095,-1.75) 50(3.095,-2.25) 51(3.095,-2.75) 52(3.095,-3.25) 53(3.095,-3.75) 54(3.095,-4.25) 55(3.095,-4.75) 56(3.095,-5.25) 57(3.095,-5.75) 58(3.095,-6.25) 59(3.095,-6.75) 60(3.095,-7.25) 61(3.095,-7.75) 62(3.095,-8.25) 63(3.095,-8.75) 64(3.095,-9.25) 65(3.095,-9.75) 66(3.095,-10.25) 67(3.095,-10.75) 68(3.095,-11.25) 69(3.095,-11.75) 70(3.095,-12.25) 71(3.095,-12.75) 72(3.095,-13.25) 73(3.095,-13.75) 74(3.095,-14.25) 75(3.095,-14.75) 76(3.095,-15.25) 77(3.095,-15.75) 78(3.095,-16.25) 79(3.095,-16.75) 80(3.095,-17.25) 81(3.095,-17.75) 82(3.095,-18.25) 83(3.095,-18.75) 84(3.095,-19.25) 85(3.095,-19.75) 86(3.095,-20.25) 87(3.095,-20.75) 88(3.095,-21.25) 89(3.095,-21.75) 90(3.095,-22.25) 91(-3.095,-22.25) 92(-3.095,-21.75) 93(-3.095,-21.25) 94(-3.095,-20.75) 95(-3.095,-20.25) 96(-3.095,-19.75) 97(-3.095,-19.25) 98(-3.095,-18.75) 99(-3.095,-18.25) 100(-3.095,-17.75) 101(-3.095,-17.25) 102(-3.095,-16.75) 103(-3.095,-16.25) 104(-3.095,-15.75) 105(-3.095,-15.25) 106(-3.095,-14.75) 107(-3.095,-14.25) 108(-3.095,-13.75) 109(-3.095,-13.25) 110(-3.095,-12.75) 111(-3.095,-12.25) 112(-3.095,-11.75) 113(-3.095,-11.25) 114(-3.095,-10.75) 115(-3.095,-10.25) 116(-3.095,-9.75) 117(-3.095,-9.25) 118(-3.095,-8.75) 119(-3.095,-8.25) 120(-3.095,-7.75) 121(-3.095,-7.25) 122(-3.095,-6.75) 123(-3.095,-6.25) 124(-3.095,-5.75) 125(-3.095,-5.25) 126(-3.095,-4.75) 127(-3.095,-4.25) 128(-3.095,-3.75) 129(-3.095,-3.25) 130(-3.095,-2.75) 131(-3.095,-2.25) 132(-3.095,-1.75) 133(-3.095,-1.25) 134(-3.095,-0.75) 135(-3.095,-0.25) 136(-3.095,0.25) 137(-3.095,0.75) 138(-3.095,1.25) 139(-3.095,1.75) 140(-3.095,2.25) 141(-3.095,2.75) 142(-3.095,3.25) 143(-3.095,3.75) 144(-3.095,4.25) 145(-3.095,4.75) 146(-3.095,5.25) 147(-3.095,5.75) 148(-3.095,6.25) 149(-3.095,6.75) 150(-3.095,7.25) 151(-3.095,7.75) 152(-3.095,8.25) 153(-3.095,8.75) 154(-3.095,9.25) 155(-3.095,9.75) 156(-3.095,10.25) 157(-3.095,10.75) 158(-3.095,11.25) 159(-3.095,11.75) 160(-3.095,12.25) 161(-3.095,12.75) 162(-3.095,13.25) 163(-3.095,13.75) 164(-3.095,14.25) 165(-3.095,14.75) 166(-3.095,15.25) 167(-3.095,15.75) 168(-3.095,16.25) 169(-3.095,16.75) 170(-3.095,17.25) 171(-3.095,17.75) 172(-3.095,18.25) 173(-3.095,18.75) 174(-3.095,19.25) 175(-3.095,19.75) 176(-3.095,20.25) 177(-3.095,20.75) 178(-3.095,21.25) 179(-3.095,21.75) 180(-3.095,22.25)
  round 1.15 hole 1.15 unplated paste-2539.97 mask+0: H1(-2.666,25.067) H2(-2.666,-25.067)
  silkscreen extent -3.25,-25.12 4.11,25.12, body extent -3.75,-25.64 3.75,25.64, height 3.25
CAPC1005L(0402) [mm] "General 0402 Capacitor Footprint, Body 1.0x0.5mm, IPC High Density"
  rect 0.6x0.5 smd: 1(-0.525,0) 2(0.525,0)
  silkscreen extent -0.97,-0.4 0.97,0.4, body extent -0.55,-0.3 0.55,0.3, height 0.6
CAPC1608L(0603) [mm] "General 0603 Capacitor Footprint, Body 1.6x0.8mm, IPC High Density"
  rect 0.8x0.8 smd: 1(-0.75,0) 2(0.75,0)
  silkscreen extent -1.3,-0.55 1.3,0.55, body extent -0.87,-0.48 0.87,0.48, height 0.85
CAPC3216L(1206) [mm] "General 1206 Capacitor Footprint, Body 3.2x1.6mm, IPC High Density"
  rect 1.1x1.7 smd: 1(-1.45,0) 2(1.45,0)
  silkscreen extent -2.15,-1 2.2,1.03, body extent -1.7,-0.9 1.7,0.9, height 1.35
DO-214AC [mm] "General DO-214AC/SMA Diode Footprint; 2 C-Bend Leads; Body 5.0 x 2.7 mm, inc. leads (LxW)"
  rect 2.4x1.8 smd: A(-2.05,0) K(2.05,0)
  silkscreen extent -3.65,-1.3 4.2,1.3, body extent -2.6,-1.45 2.6,1.45, height 2.3
Fiducial050 [mm] "Fiducial for pick&place, Diameter 0.5mm"
  round 0.5 smd mask+0.5: 0(0,0)
  silkscreen extent -1.5,-1.5 1.5,1.5
FP-BNX02-MFG [mm] "BNX02 Package"
  rect 3.8x2.5 smd paste+0 mask+0: 1(-6.85,2.15) 2(6.85,2.15) 3(-6.85,-2.15) 4(6.85,-2.15)
  rect 7.9x2.3 smd paste+0 mask+0: 4(1,-5.05)
  rect 3.4x2.3 smd paste+0 mask+0: 4(3.25,5.1)
  silkscreen extent -9.45,-4.65 6.15,4.65, body extent -6.05,-4.55 6.05,4.55, height 3.35
"Inductor 8400 Serie" [mm] "Precision Wire Wound Inductor, 2-Leads, Body 4.50x3.30mm"
  rect 2x3.5 smd: 1(-1.6,0) 2(1.6,0)
  silkscreen extent -2.9,-2 2.9,2, body extent -2.32,-1.73 2.32,1.72, height 2.6
LD09P33E4GV00LF [mm] "Conn D-Subminiature PIN 9 POS 2.74mm Solder RA Thru-Hole 9 Terminal 1 Port"
  rect 1.4x1.4 hole 0.9: 1(0,0)
  round 1.4 hole 0.9: 2(2.74,0) 3(5.48,0) 4(8.22,0) 5(10.96,0) 6(1.37,-2.84) 7(4.11,-2.84) 8(6.85,-2.84) 9(9.59,-2.84)
  round 4.65 hole 3.1: MH1(-7.015,-1.42) MH2(17.975,-1.42)
  silkscreen extent -0.1,2 0.1,2.2, body extent -9.94,-17.15 20.87,1.7, height 12.55
LED0603_GREEN [mm] "General LED (green) 0603 Footprint"
  rect 0.7x0.9 smd: A(-0.75,0) K(0.75,0)
  silkscreen extent -0.23,-0.51 1.4,0.51, body extent -0.85,-0.48 0.85,0.48, height 0.6
LMR43610MSC3RPERQ1 [mm]
  round 0.025 smd paste-2539.97: 1(-0.825,0.913) 8(0.825,0.913) 9(0,0.55)
  rrect50% 0.6x0.25 smd paste+0: 2(-0.9,0.25) 3(-0.9,-0.25) 6(0.9,-0.25) 7(0.9,0.25)
  round 0.025 smd: 4(-0.825,-0.913) 5(0.825,-0.913)
  Top Layer region: -0.125,-0.1 -0.144,-0.096 -0.16,-0.085 -0.171,-0.069 -0.175,-0.05 -0.175,-0.05 -0.175,1.15 -0.171,1.169 -0.16,1.185 -0.144,1.196 -0.125,1.2 -0.125,1.2 0.125,1.2 0.125,1.2 0.144,1.196 0.16,1.185 0.171,1.169 0.175,1.15 0.175,1.15 0.175,1.15 0.175,-0.05 0.175,-0.05 0.171,-0.069 0.16,-0.085 0.144,-0.096 0.125,-0.1 0.125,-0.1
  Top Layer region: -1.2,0.675 -1.2,0.8 -1.2,0.8 -1.196,0.819 -1.185,0.835 -1.169,0.846 -1.15,0.85 -1.15,0.85 -0.9,0.85 -0.9,0.85 -0.881,0.854 -0.865,0.865 -0.854,0.881 -0.85,0.9 -0.85,0.9 -0.85,1.15 -0.85,1.15 -0.846,1.169 -0.835,1.185 -0.819,1.196 -0.8,1.2 -0.8,1.2 -0.5,1.2 -0.5,1.2 -0.481,1.196 -0.465,1.185 -0.454,1.169 -0.45,1.15 -0.45,1.15 -0.45,0.675 -0.45,0.675 -0.454,0.656 -0.465,0.64 -0.481,0.629 -0.5,0.625 -0.5,0.625 -1.15,0.625 -1.15,0.625 -1.169,0.629 -1.185,0.64 -1.196,0.656 -1.2,0.675
  Top Layer region: 1.2,0.675 1.2,0.8 1.2,0.8 1.196,0.819 1.185,0.835 1.169,0.846 1.15,0.85 1.15,0.85 0.9,0.85 0.9,0.85 0.881,0.854 0.865,0.865 0.854,0.881 0.85,0.9 0.85,0.9 0.85,1.15 0.85,1.15 0.846,1.169 0.835,1.185 0.819,1.196 0.8,1.2 0.8,1.2 0.5,1.2 0.5,1.2 0.481,1.196 0.465,1.185 0.454,1.169 0.45,1.15 0.45,1.15 0.45,0.675 0.45,0.675 0.454,0.656 0.465,0.64 0.481,0.629 0.5,0.625 0.5,0.625 1.15,0.625 1.15,0.625 1.169,0.629 1.185,0.64 1.196,0.656 1.2,0.675
  Top Layer region: 1.2,-0.675 1.2,-0.8 1.2,-0.8 1.196,-0.819 1.185,-0.835 1.169,-0.846 1.15,-0.85 1.15,-0.85 0.9,-0.85 0.9,-0.85 0.881,-0.854 0.865,-0.865 0.854,-0.881 0.85,-0.9 0.85,-0.9 0.85,-1.15 0.85,-1.15 0.846,-1.169 0.835,-1.185 0.819,-1.196 0.8,-1.2 0.8,-1.2 0.5,-1.2 0.5,-1.2 0.481,-1.196 0.465,-1.185 0.454,-1.169 0.45,-1.15 0.45,-1.15 0.45,-0.675 0.45,-0.675 0.454,-0.656 0.465,-0.64 0.481,-0.629 0.5,-0.625 0.5,-0.625 1.15,-0.625 1.15,-0.625 1.169,-0.629 1.185,-0.64 1.196,-0.656 1.2,-0.675
  Top Layer region: -1.2,-0.675 -1.2,-0.8 -1.2,-0.8 -1.196,-0.819 -1.185,-0.835 -1.169,-0.846 -1.15,-0.85 -1.15,-0.85 -0.9,-0.85 -0.9,-0.85 -0.881,-0.854 -0.865,-0.865 -0.854,-0.881 -0.85,-0.9 -0.85,-0.9 -0.85,-1.15 -0.85,-1.15 -0.846,-1.169 -0.835,-1.185 -0.819,-1.196 -0.8,-1.2 -0.8,-1.2 -0.5,-1.2 -0.5,-1.2 -0.481,-1.196 -0.465,-1.185 -0.454,-1.169 -0.45,-1.15 -0.45,-1.15 -0.45,-0.675 -0.45,-0.675 -0.454,-0.656 -0.465,-0.64 -0.481,-0.629 -0.5,-0.625 -0.5,-0.625 -1.15,-0.625 -1.15,-0.625 -1.169,-0.629 -1.185,-0.64 -1.196,-0.656 -1.2,-0.675
  silkscreen extent -1.4,-1.4 1.4,1.4, body extent -1,-1 1,1, height 1
M20-9731045 [mm] "Connector Header Through Hole 10 position 0.100\" (2.54mm)"
  rect 1.8x1.8 hole 1: 1(0,0)
  round 1.8 hole 1: 2(-2.54,0) 3(-5.08,0) 4(-7.62,0) 5(-10.16,0) 6(-12.7,0) 7(-15.24,0) 8(-17.78,0) 9(-20.32,0) 10(-22.86,0)
  silkscreen extent -24.26,-1.27 1.25,1.27, body extent -24.13,-1.27 1.27,1.27, height 8.74
M20-9990245 [mm] "Connector Header Through Hole 2 position 0.100\" (2.54mm)"
  rect 1.8x1.8 hole 1: 1(0,0)
  round 1.8 hole 1: 2(-2.54,0)
  silkscreen extent -3.81,-1.27 1.27,1.27, body extent -3.81,-1.27 1.27,1.27, height 8.74
PJ-002AH-SMT-TR [mm] "2.0 x 6.5 mm, 5.0 A, Horizontal, Surface Mount (SMT), Dc Power Jack Connector"
  rect 2.8x2.4 smd: 1(-6.1,0) 1(0,0) 3(0,-11.4)
  rect 2.8x2.4 smd mask+0: 2(-6.1,-11.4)
  round 1.7 hole 1.7 unplated: NC(-6.1,-5.7)
  round 1.8 hole 1.8 unplated: NC(-1.6,-5.7)
  silkscreen extent -4.5,-10.2 0.2,1.9, body extent -11.1,-12 3.7,0.6, height 11
"PTC Fuse(1812)" [mm] "1812 PTC Fuse Footprint, Body 4.5x3.2mm, IPC High Density"
  rect 1.68x3.15 smd: 1(-2.39,0) 2(2.39,0)
  silkscreen extent -1.1,-1.55 1.1,1.55, body extent -2.4,-1.7 2.4,1.7, height 0.7
QFN50P300X300-16WAL [mm] "General QFN Footprint, 16-Leads, Body 3.00x3.00mm, Pitch 0.50mm, Thermal Pad 1.60x1.60mm, IPC High Density"
  oval 0.7x0.25 smd: 1(-1.45,0.75) 2(-1.45,0.25) 3(-1.45,-0.25) 4(-1.45,-0.75) 9(1.45,-0.75) 10(1.45,-0.25) 11(1.45,0.25) 12(1.45,0.75)
  oval 0.25x0.7 smd: 5(-0.75,-1.45) 6(-0.25,-1.45) 7(0.25,-1.45) 8(0.75,-1.45) 13(0.75,1.45) 14(0.25,1.45) 15(-0.25,1.45) 16(-0.75,1.45)
  rect 1.6x1.6 smd: 17(0,0)
  silkscreen extent -2.47,-1.6 1.6,1.6, body extent -1.58,-1.58 1.58,1.58, height 0.8
RESC1005L(0402) [mm] "General 0402 Resistor Footprint, Body 1.1x0.5mm, IPC High Density"
  rect 0.6x0.6 smd: 1(-0.5,0) 2(0.5,0)
  silkscreen extent -1.02,-0.43 1.02,0.43, body extent -0.55,-0.3 0.55,0.3, height 0.4
RESC1608L(0603) [mm] "General 0603 Resistor Footprint, Body 1.6x0.8mm, IPC High Density"
  rect 0.7x0.9 smd: 1(-0.75,0) 2(0.75,0)
  silkscreen extent -1.35,-0.6 1.35,0.6, body extent -0.85,-0.48 0.85,0.48, height 0.6
RESC2012L(0805) [mm] "General 0805 Resistor Footprint, Body 2.0x1.3mm, IPC High Density"
  rect 1x1.3 smd: 1(-0.8,0) 2(0.8,0)
  silkscreen extent -1.6,-0.8 1.6,0.8, body extent -1.07,-0.7 1.07,0.7, height 0.65
RESQUAD0804 [mm] "General 0804 Quad Resisor Array Footprint, Body 2.0x1.2mm"
  rect 0.4x0.5 smd: 1(-0.8,-0.5) 4(0.8,-0.5) 5(0.8,0.5) 8(-0.8,0.5)
  rect 0.3x0.5 smd: 2(-0.25,-0.5) 3(0.25,-0.5) 6(0.25,0.5) 7(-0.25,0.5)
  silkscreen extent -1.2,-0.5 1.2,0.5, body extent -1,-0.5 1,0.5, height 0.4
RESQUAD1206 [mm] "General 1206 Quad Resisor Array Footprint, Body 3.2x1.6mm"
  rect 0.64x0.7 smd: 1(-1.27,-0.7) 4(1.27,-0.7) 5(1.27,0.7) 8(-1.27,0.7)
  rect 0.5x0.7 smd: 2(-0.4,-0.7) 3(0.4,-0.7) 6(0.4,0.7) 7(-0.4,0.7)
  silkscreen extent -1.75,-0.75 1.75,0.75, body extent -1.5,-0.75 1.5,0.75, height 0.4
ROE [mm] "RECOM DC/DC Converter Series - ROE Series Footprint"
  rect 1.338x1.338 hole 0.83: 1(-3.875,-1.75)
  round 1.338 hole 0.83: 2(-1.335,-1.75) 3(1.205,-1.75) 4(3.745,-1.75)
  silkscreen extent -6.51,-3 5.72,3, body extent -5.78,-3 5.72,3, height 10
SOIC127P600-8AL [mm] "General SOIC Footprint, 8-Leads, Body 4.90x3.90mm, Pitch 1.27mm, IPC High Density"
  oval 1.7x0.6 smd: 1(-2.45,1.905) 2(-2.45,0.635) 3(-2.45,-0.635) 4(-2.45,-1.905) 5(2.45,-1.905) 6(2.45,-0.635) 7(2.45,0.635) 8(2.45,1.905)
  silkscreen extent -2.57,-2.5 1.2,2.88, body extent -3,-2.5 3,2.5, height 1.75
SOT23-5AL [mm] "General SOT23-5 Footprint, 5-Leads, Body 2.90x1.60mm, Pitch 0.95mm, IPC High Density"
  rect 0.9x0.65 smd: 1(-1.2,0.95) 2(-1.2,0) 3(-1.2,-0.95) 4(1.2,-0.95) 5(1.2,0.95)
  silkscreen extent -1.33,-1.55 0.35,1.95, body extent -0.9,-1.55 0.9,1.55, height 1.45
SOT23-6N [mm] "General SOT23-6 Footprint, 6-Leads, Body 2.90x2.90mm, Pitch 0.95mm, IPC Medium Density"
  rect 0.8x0.5 smd: 1(-1.2,0.95) 2(-1.2,0) 3(-1.2,-0.95) 4(1.2,-0.95) 5(1.2,0) 6(1.2,0.95)
  silkscreen extent -2.07,-1.55 0.6,1.55, body extent -0.9,-1.55 0.9,1.55, height 1.2
"Spacer M3 connected" [mm] "Hole and pad for spacer M3, Sw=5.5mm"
  round 7 hole 3.2: 1(0,0)
  silkscreen extent -3.8,-3.8 3.8,3.8
TO263-3 [mm] "General TO263-3 Footprint, 3-Leads, Body 10.00x15.00mm, Pitch 2.54mm (D2PAK)"
  rect 1.6x3.8 smd: 1(-2.54,0) 2(0,0) 3(2.54,0)
  rect 10.2x8.6 smd: 2(0,9.7)
  silkscreen extent -5.07,4.58 5.07,5.25, body extent -4.91,-1.06 4.91,13.54, height 4.22
TP-3216L(1206) [mm] "General 1206 Testpoint Footprint, 3.2x1.6mm, IPC High Density"
  rect 4x1.8 smd: 1(0,0)
  silkscreen extent -2.2,-1.1 2.2,1.1, body extent -1.6,-0.8 1.6,0.8, height 1.28
TSOP65P490-8AL [mm] "General TSOP Footprint, 8-Leads, Body 3.00x3.00mm, Pitch 0.65mm, IPC High Density"
  oval 1.4x0.45 smd: 1(-2.05,0.975) 2(-2.05,0.325) 3(-2.05,-0.325) 4(-2.05,-0.975) 5(2.05,-0.975) 6(2.05,-0.325) 7(2.05,0.325) 8(2.05,0.975)
  silkscreen extent -2.17,-1.55 0.95,1.87, body extent -2.45,-1.55 2.45,1.55, height 1.1
TSSOP65P640-14N [mm] "General TSSOP Footprint, 14-Leads, Body 5.00x4.50mm, Pitch 1.00mm, IPC Medium Density"
  oval 1.4x0.396 smd: 1(-2.95,1.95) 2(-2.95,1.3) 3(-2.95,0.65) 4(-2.95,0) 5(-2.95,-0.65) 6(-2.95,-1.3) 7(-2.95,-1.95) 8(2.95,-1.95) 9(2.95,-1.3) 10(2.95,-0.65) 11(2.95,0) 12(2.95,0.65) 13(2.95,1.3) 14(2.95,1.95)
  silkscreen extent -3.07,-2.55 1.85,2.85, body extent -2.25,-2.55 2.25,2.55, height 1.2
VLS6045EX [mm] "VLS-EX series -  TDK Inductors for power circuits"
  rect 1.9x5.1 smd paste+0 mask+0: 1(-2.1,0) 2(2.1,0)
  silkscreen extent -1.12,-3 1.12,3, body extent -3,-3 3,3, height 4.5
